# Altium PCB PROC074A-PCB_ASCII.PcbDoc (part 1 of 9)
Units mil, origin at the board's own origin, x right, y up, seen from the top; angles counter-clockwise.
Board outline 2755.91 x 5300 mil, 10 copper layers (Top Layer, L2-GND, L3-SIG1, L4-GND, L5-PWR/SIG, L6-SIG2, L7-PWR2, L8-SIG3, L9-GND, Bottom Layer), stack 67.57 mil thick; 586 components, 490 nets, 2137 pads, 1150 vias.
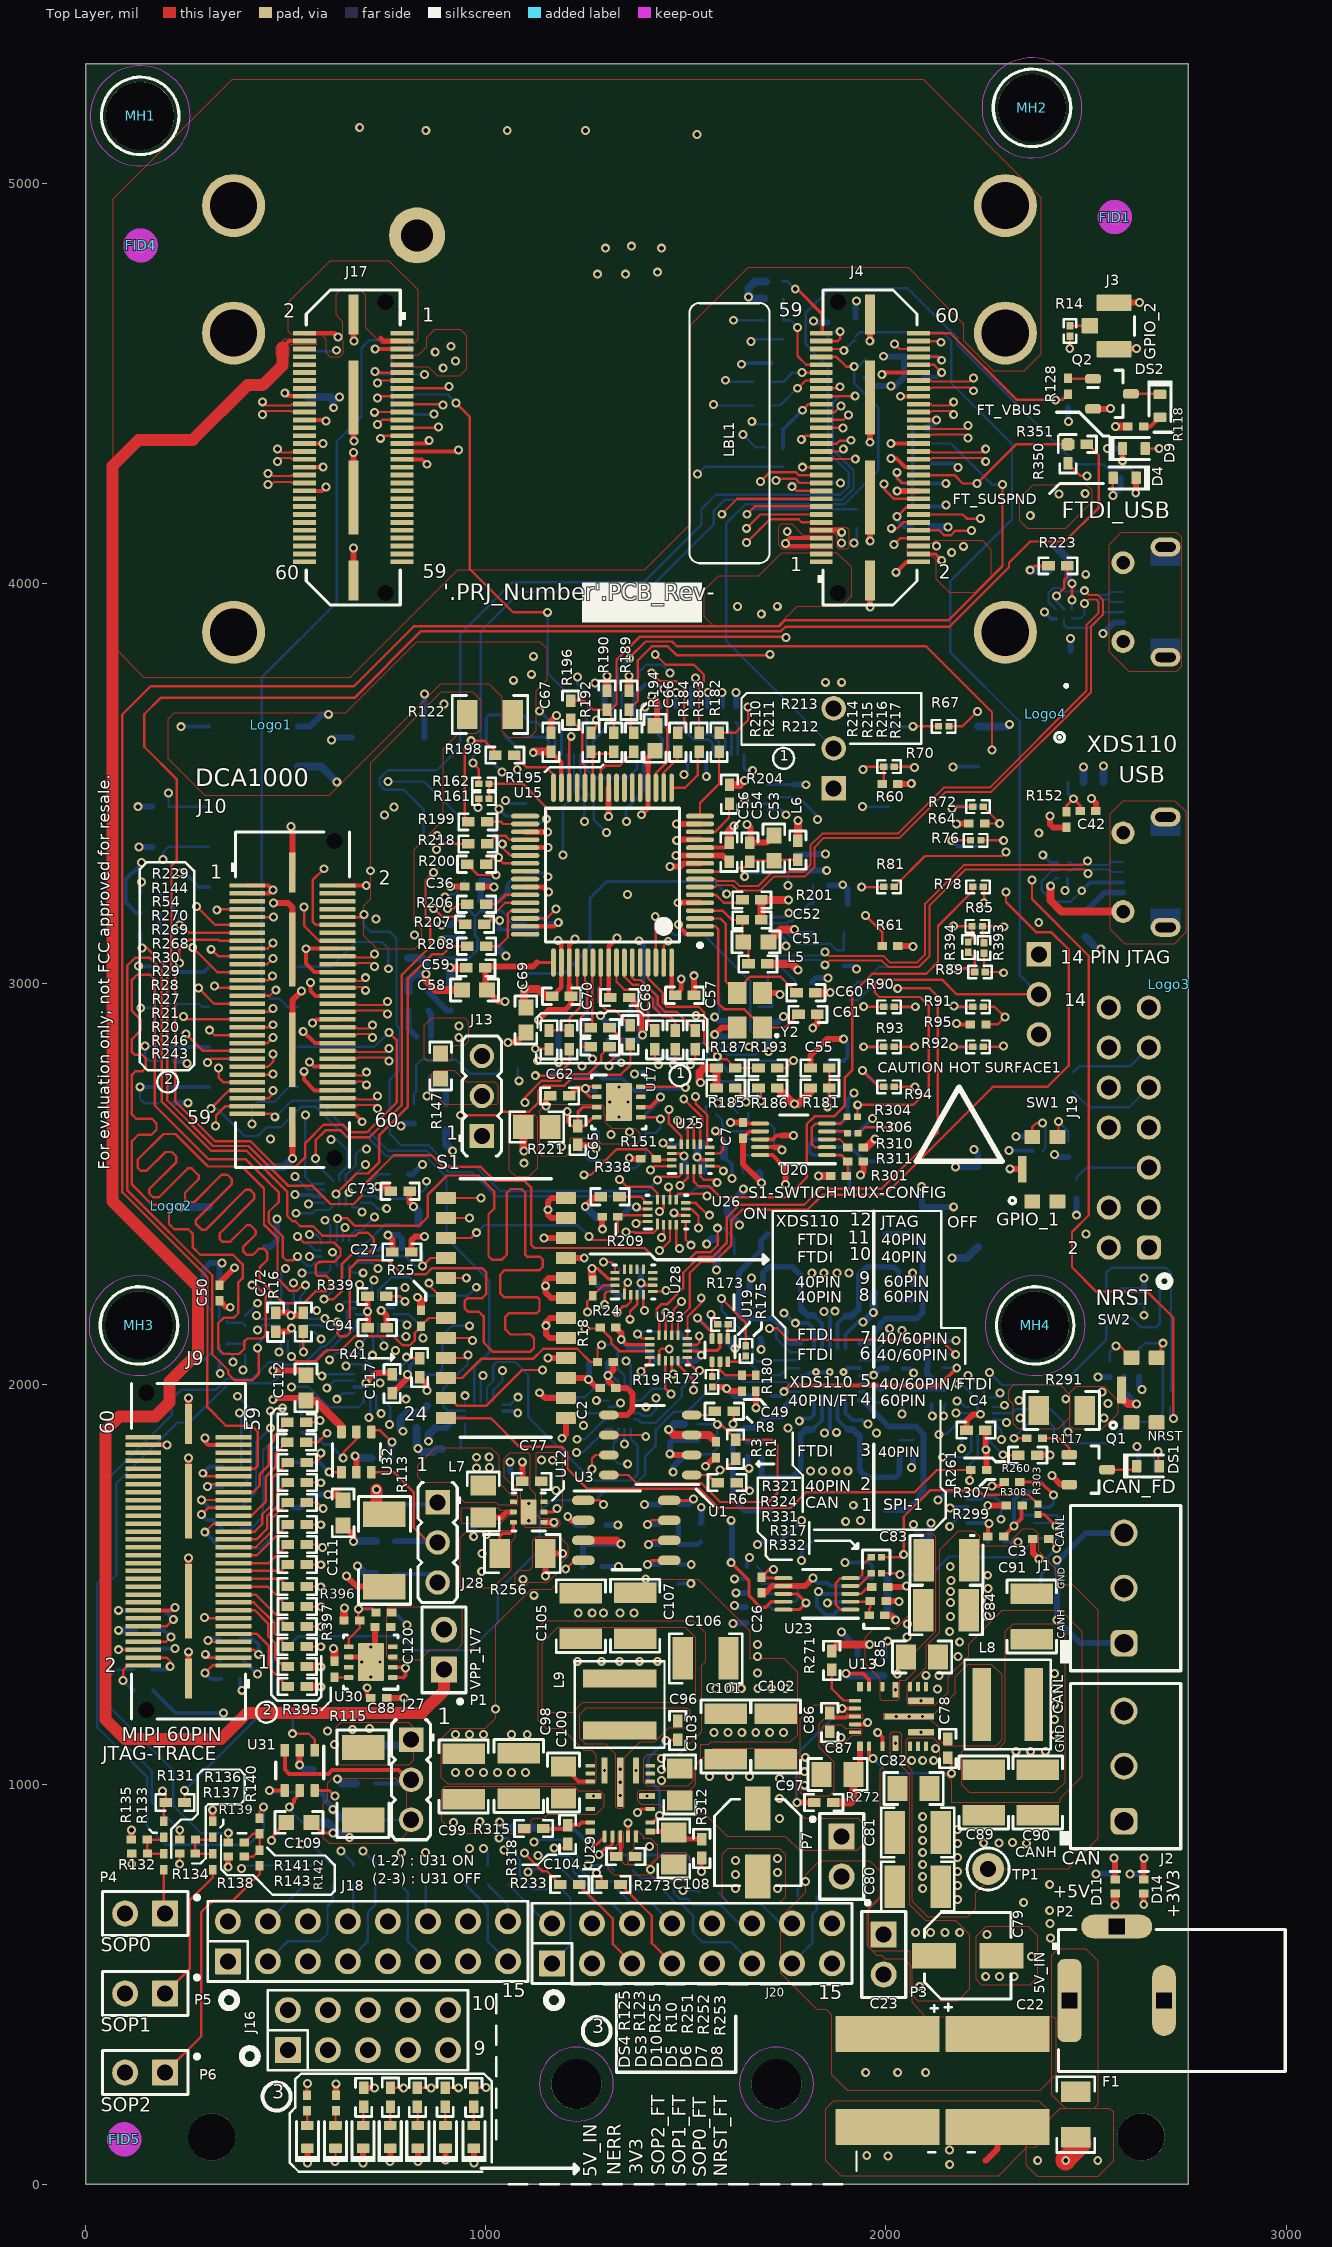
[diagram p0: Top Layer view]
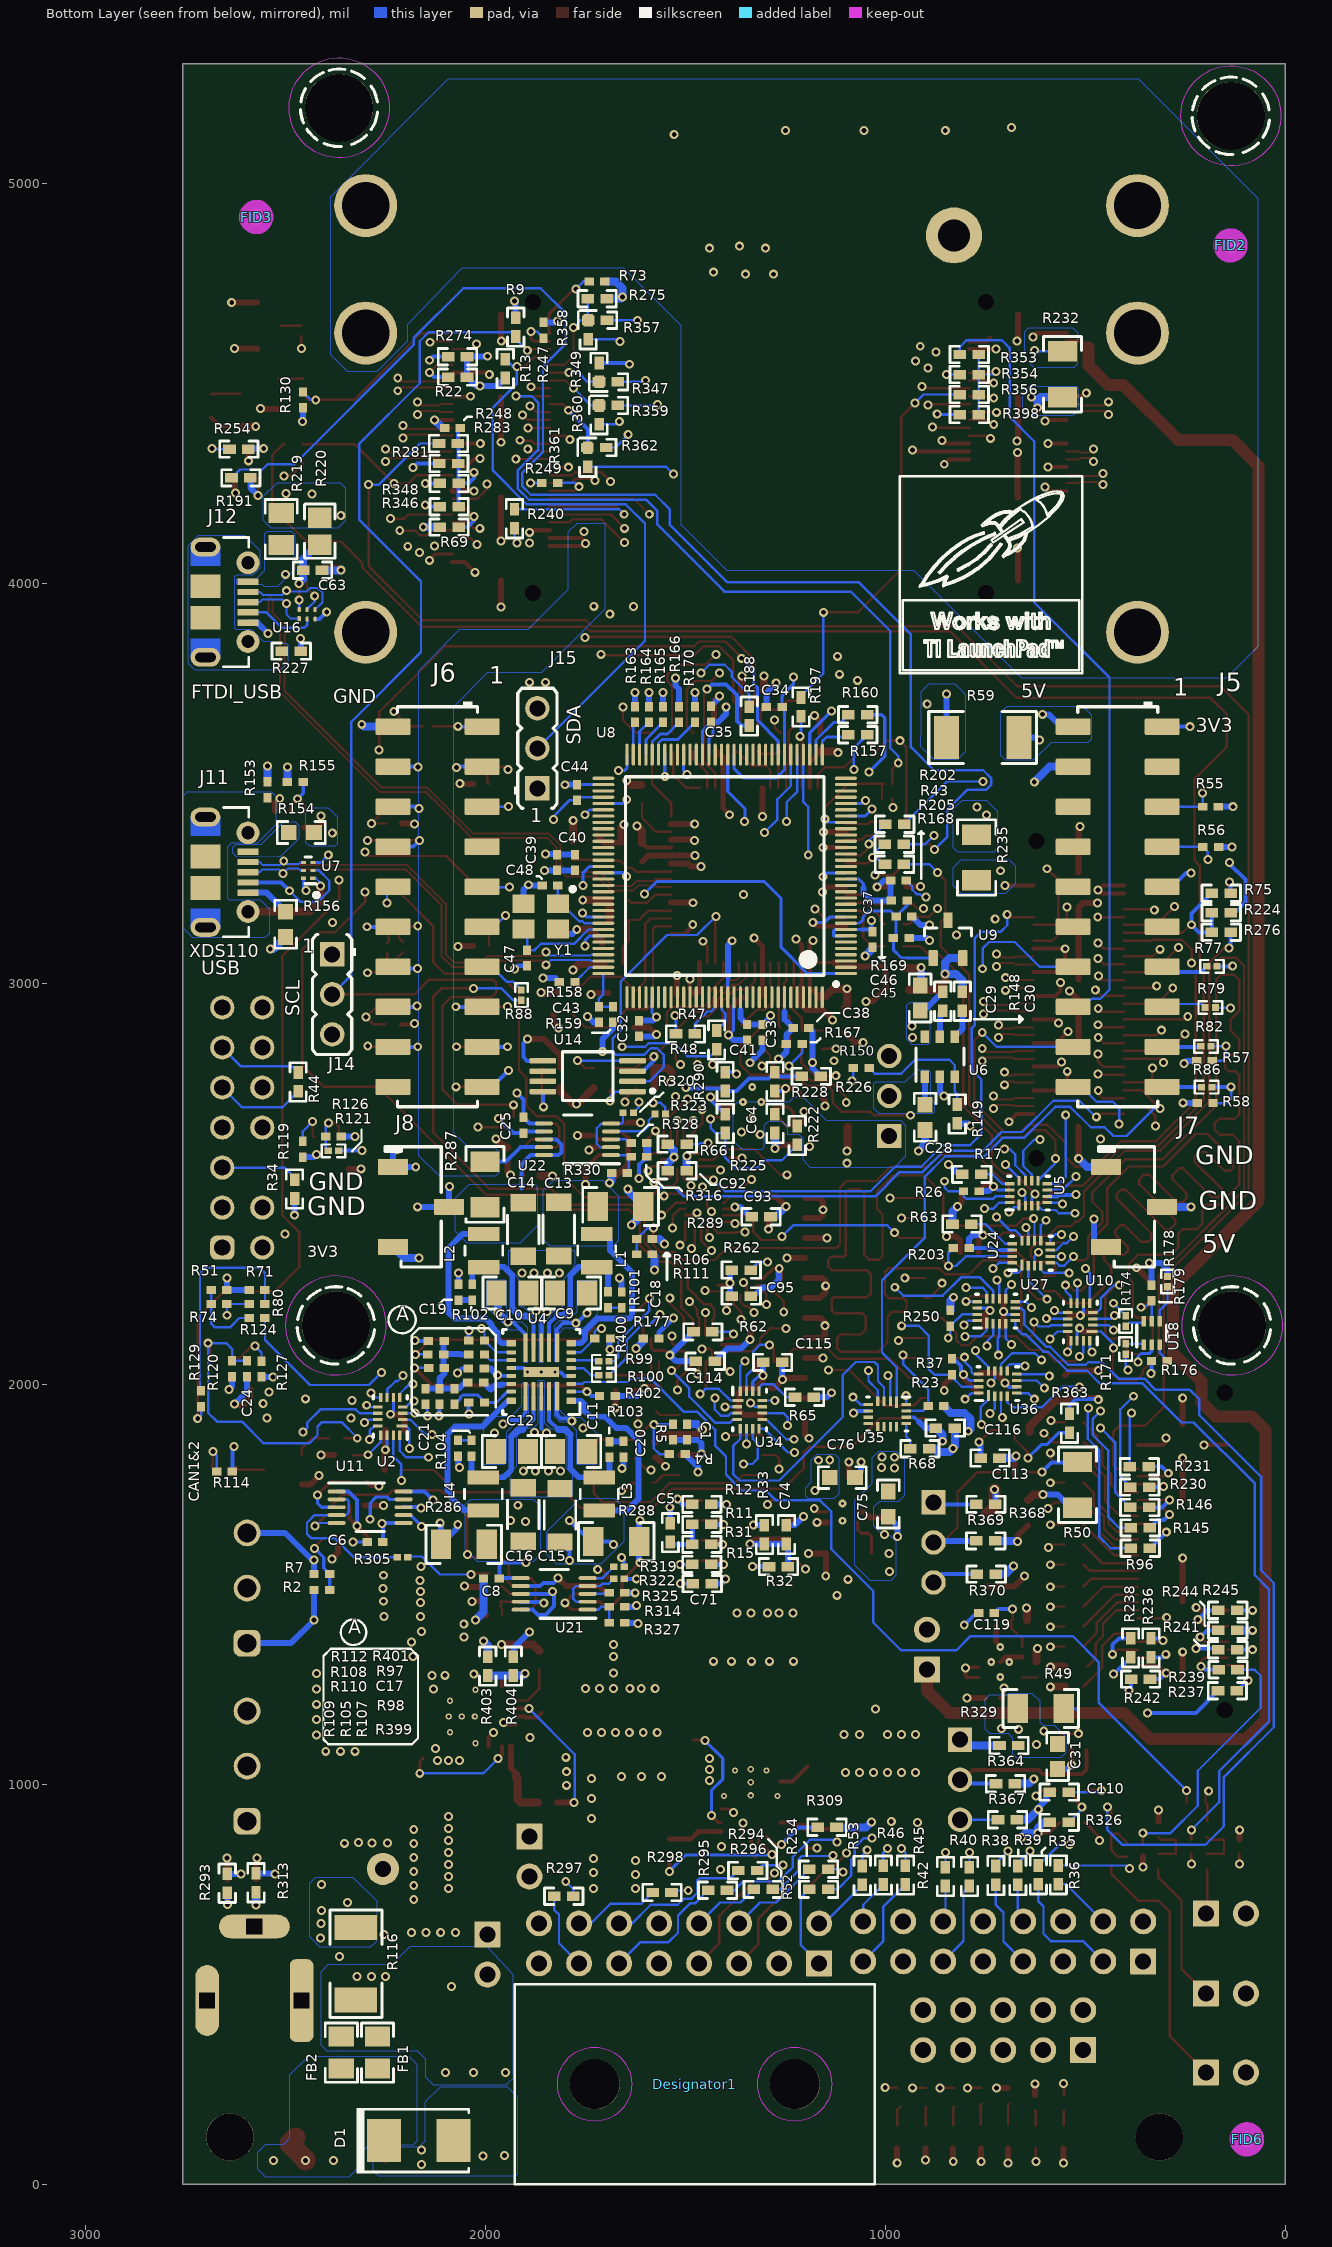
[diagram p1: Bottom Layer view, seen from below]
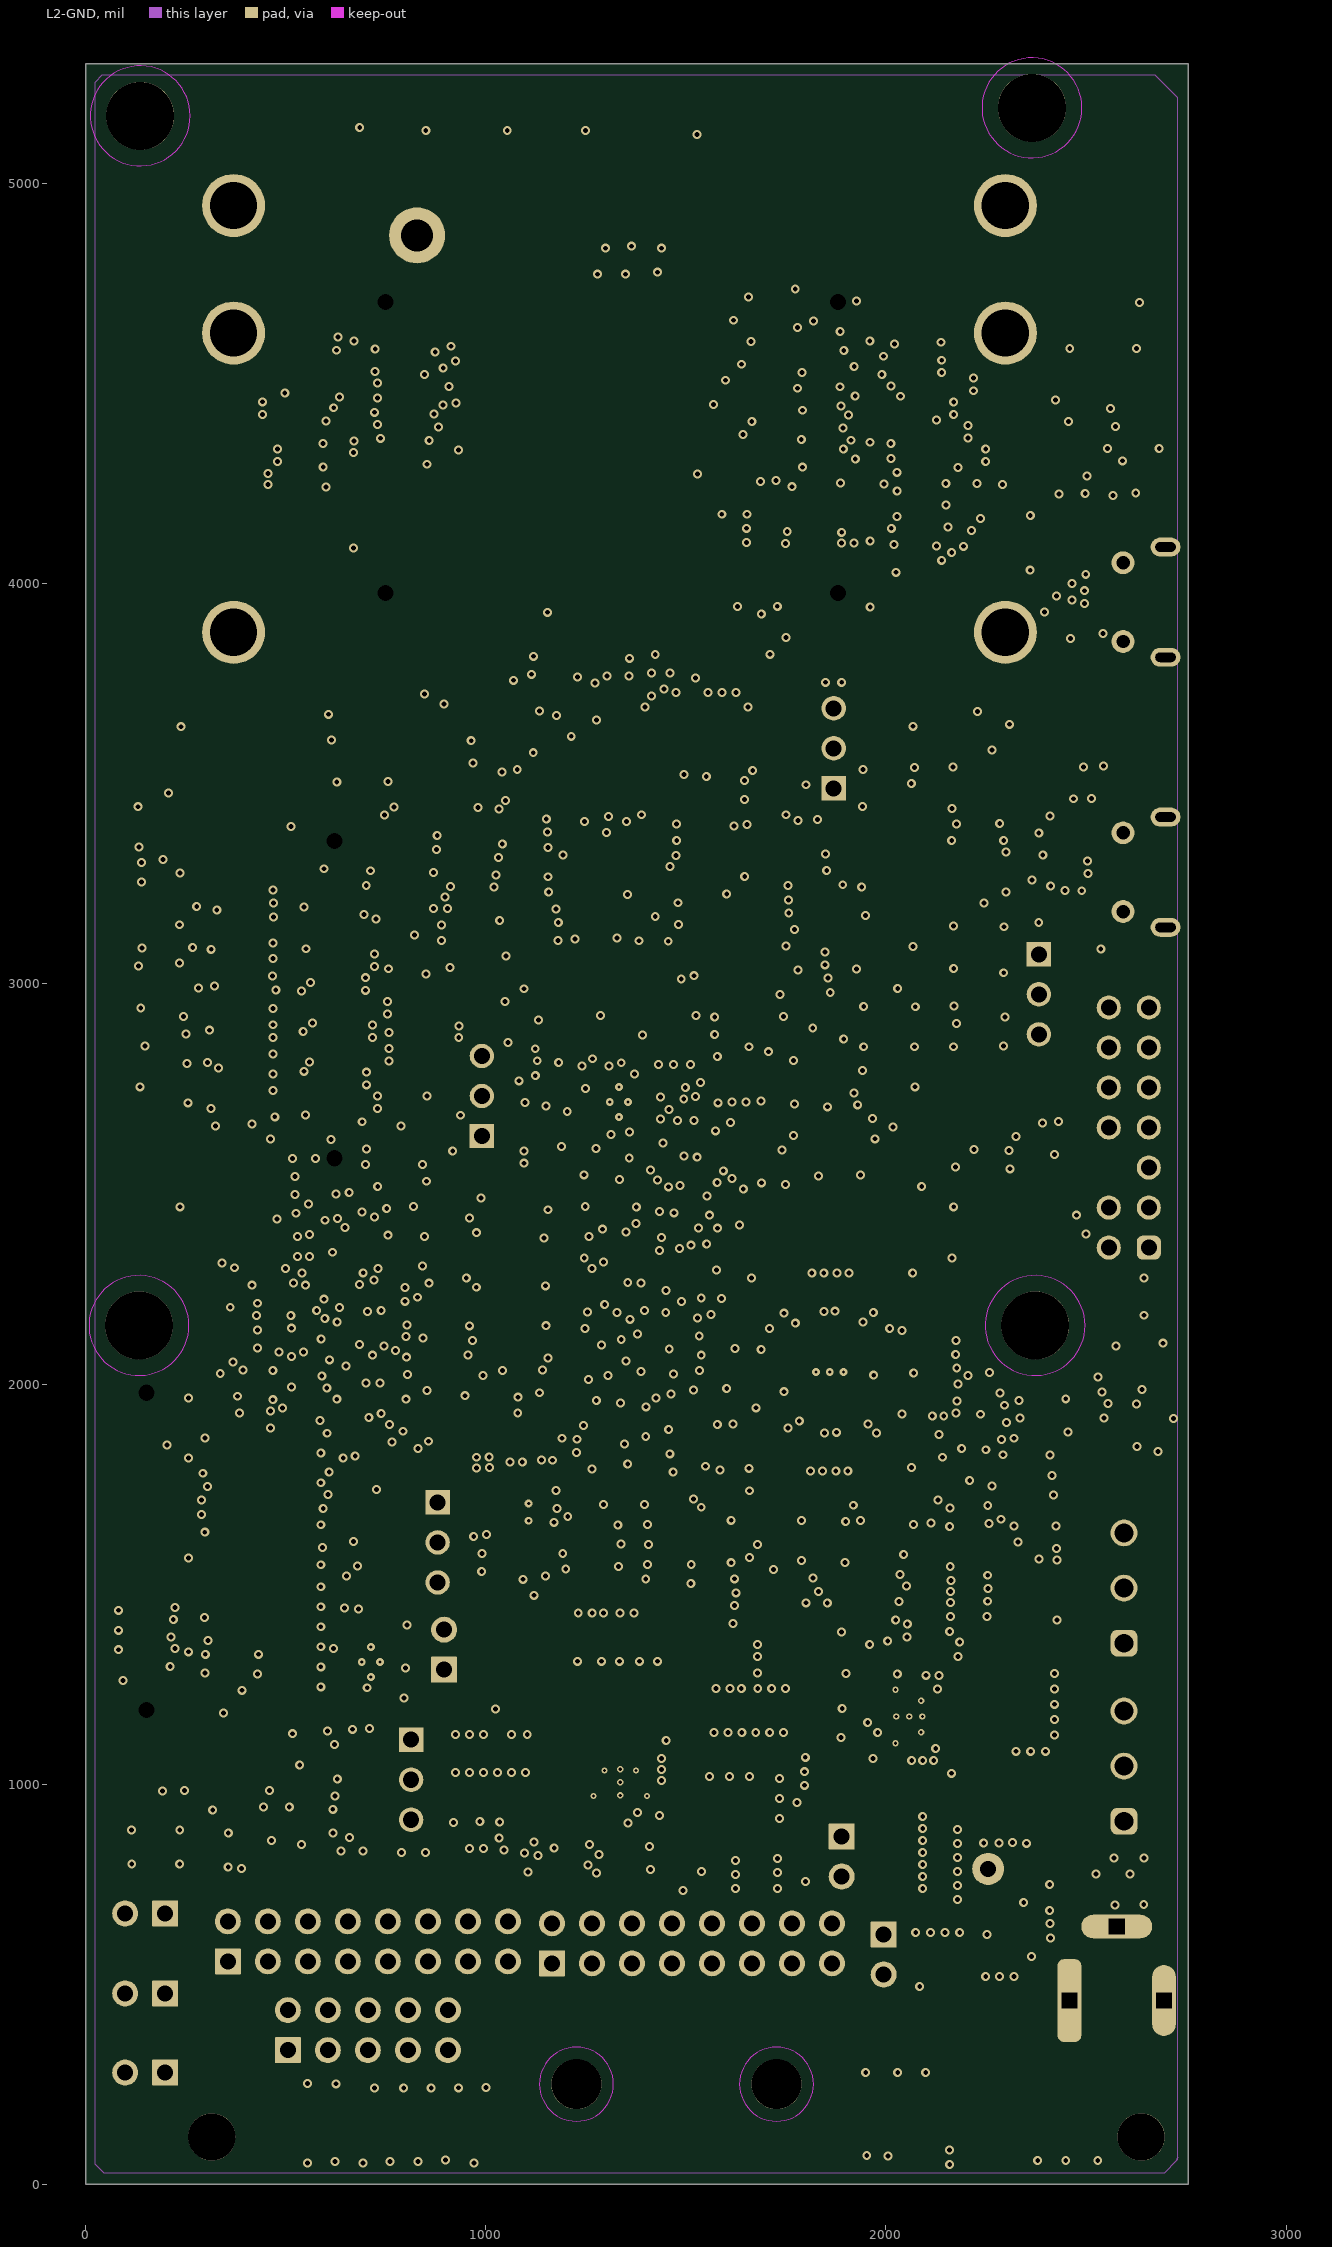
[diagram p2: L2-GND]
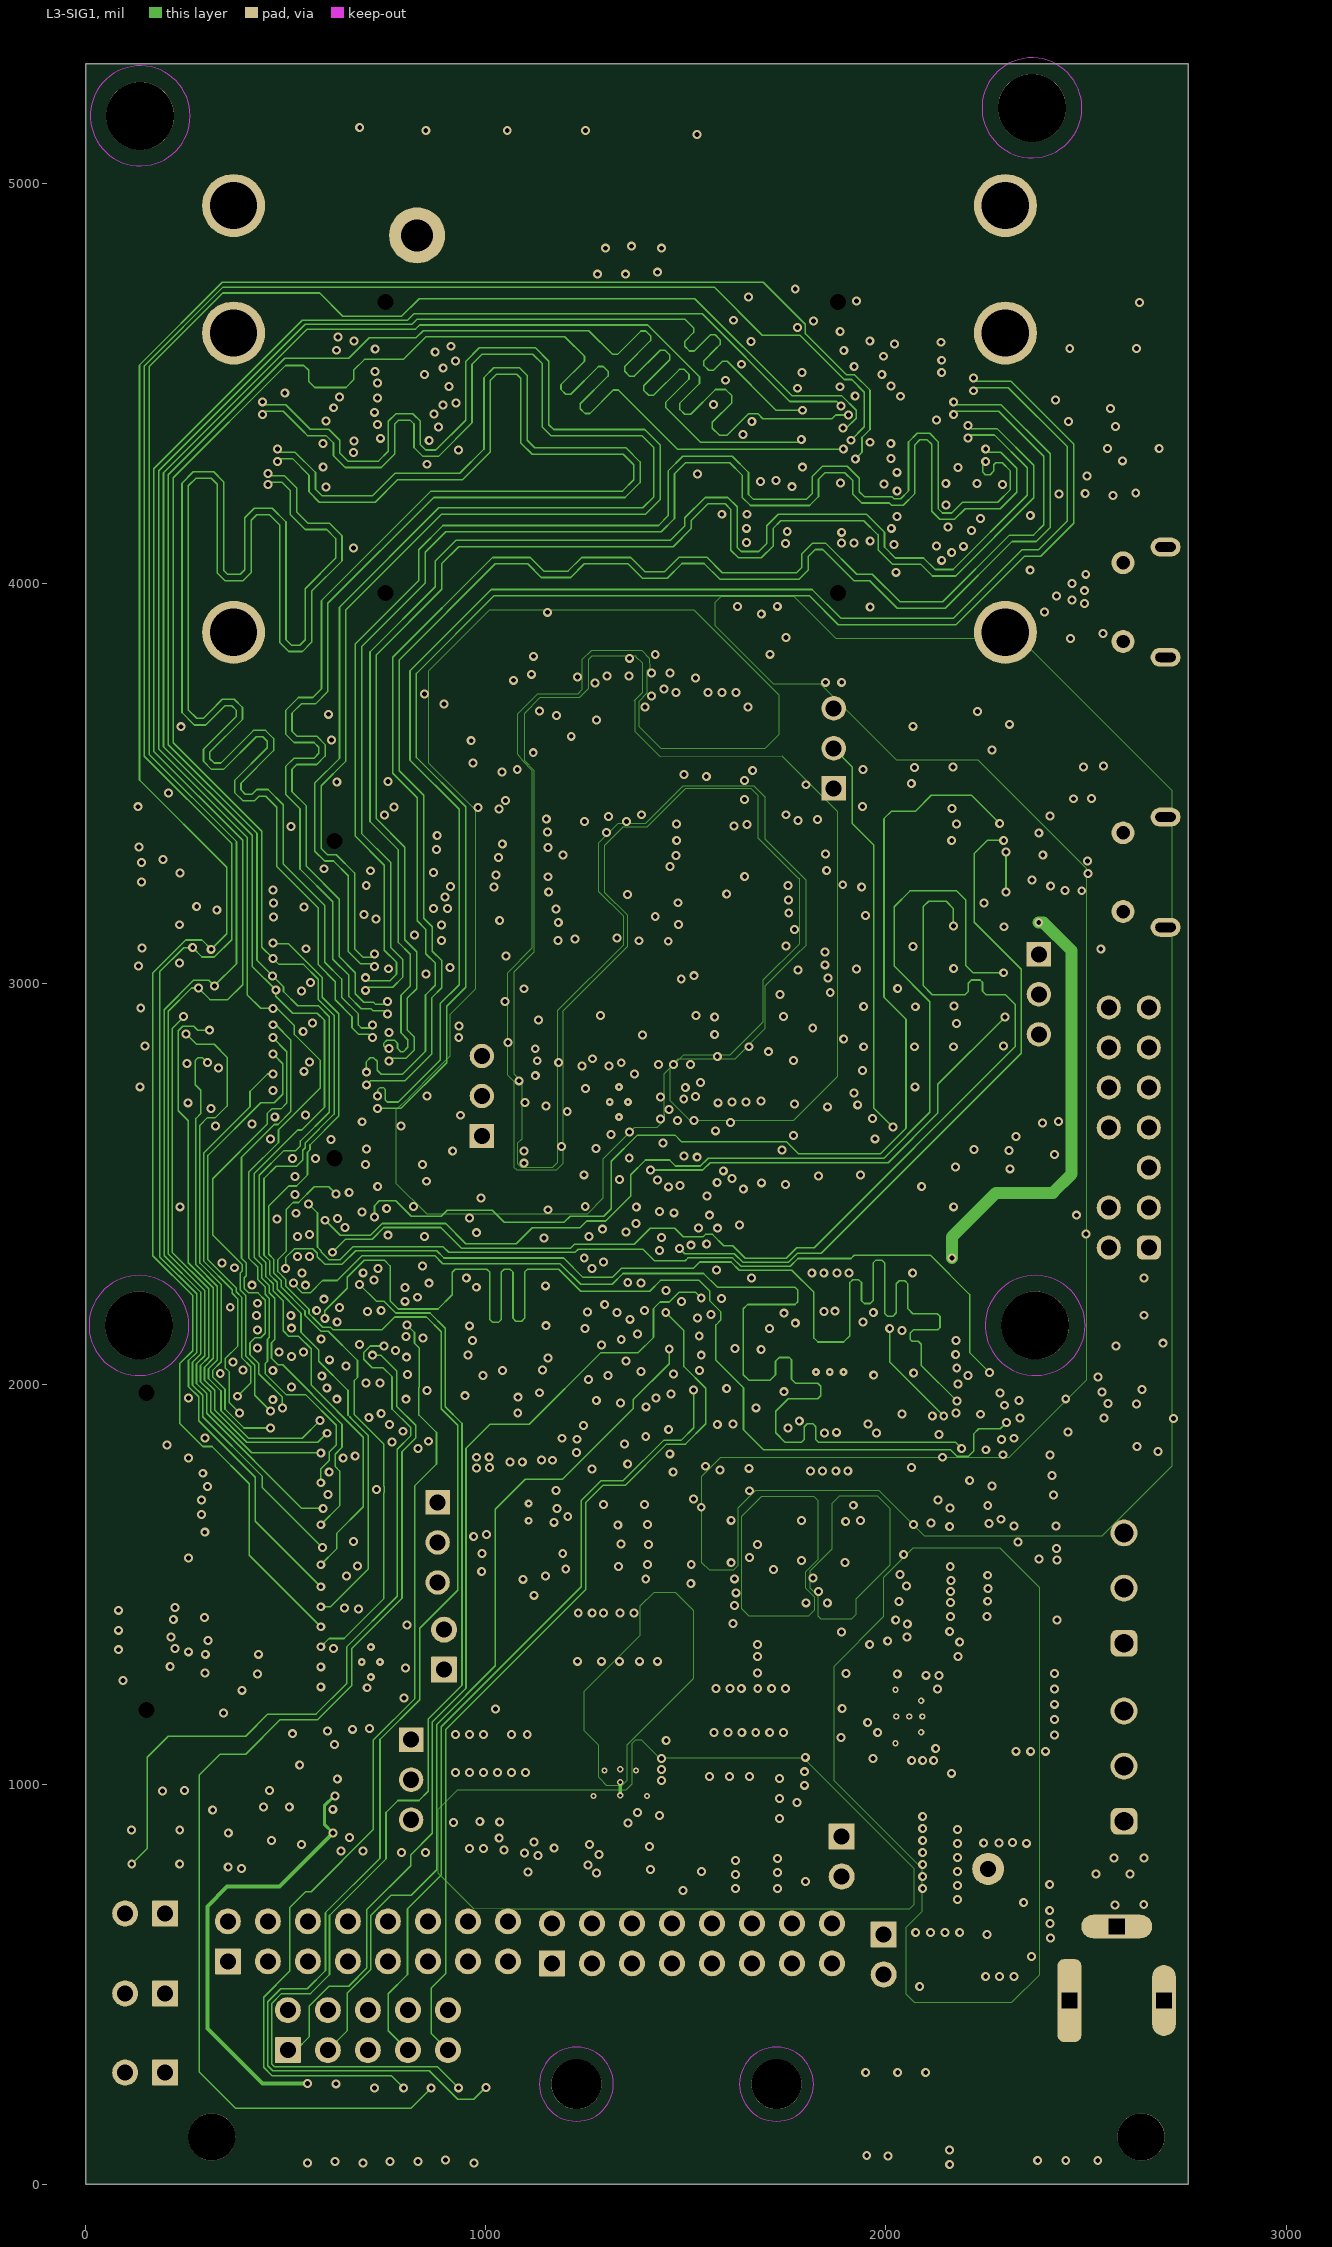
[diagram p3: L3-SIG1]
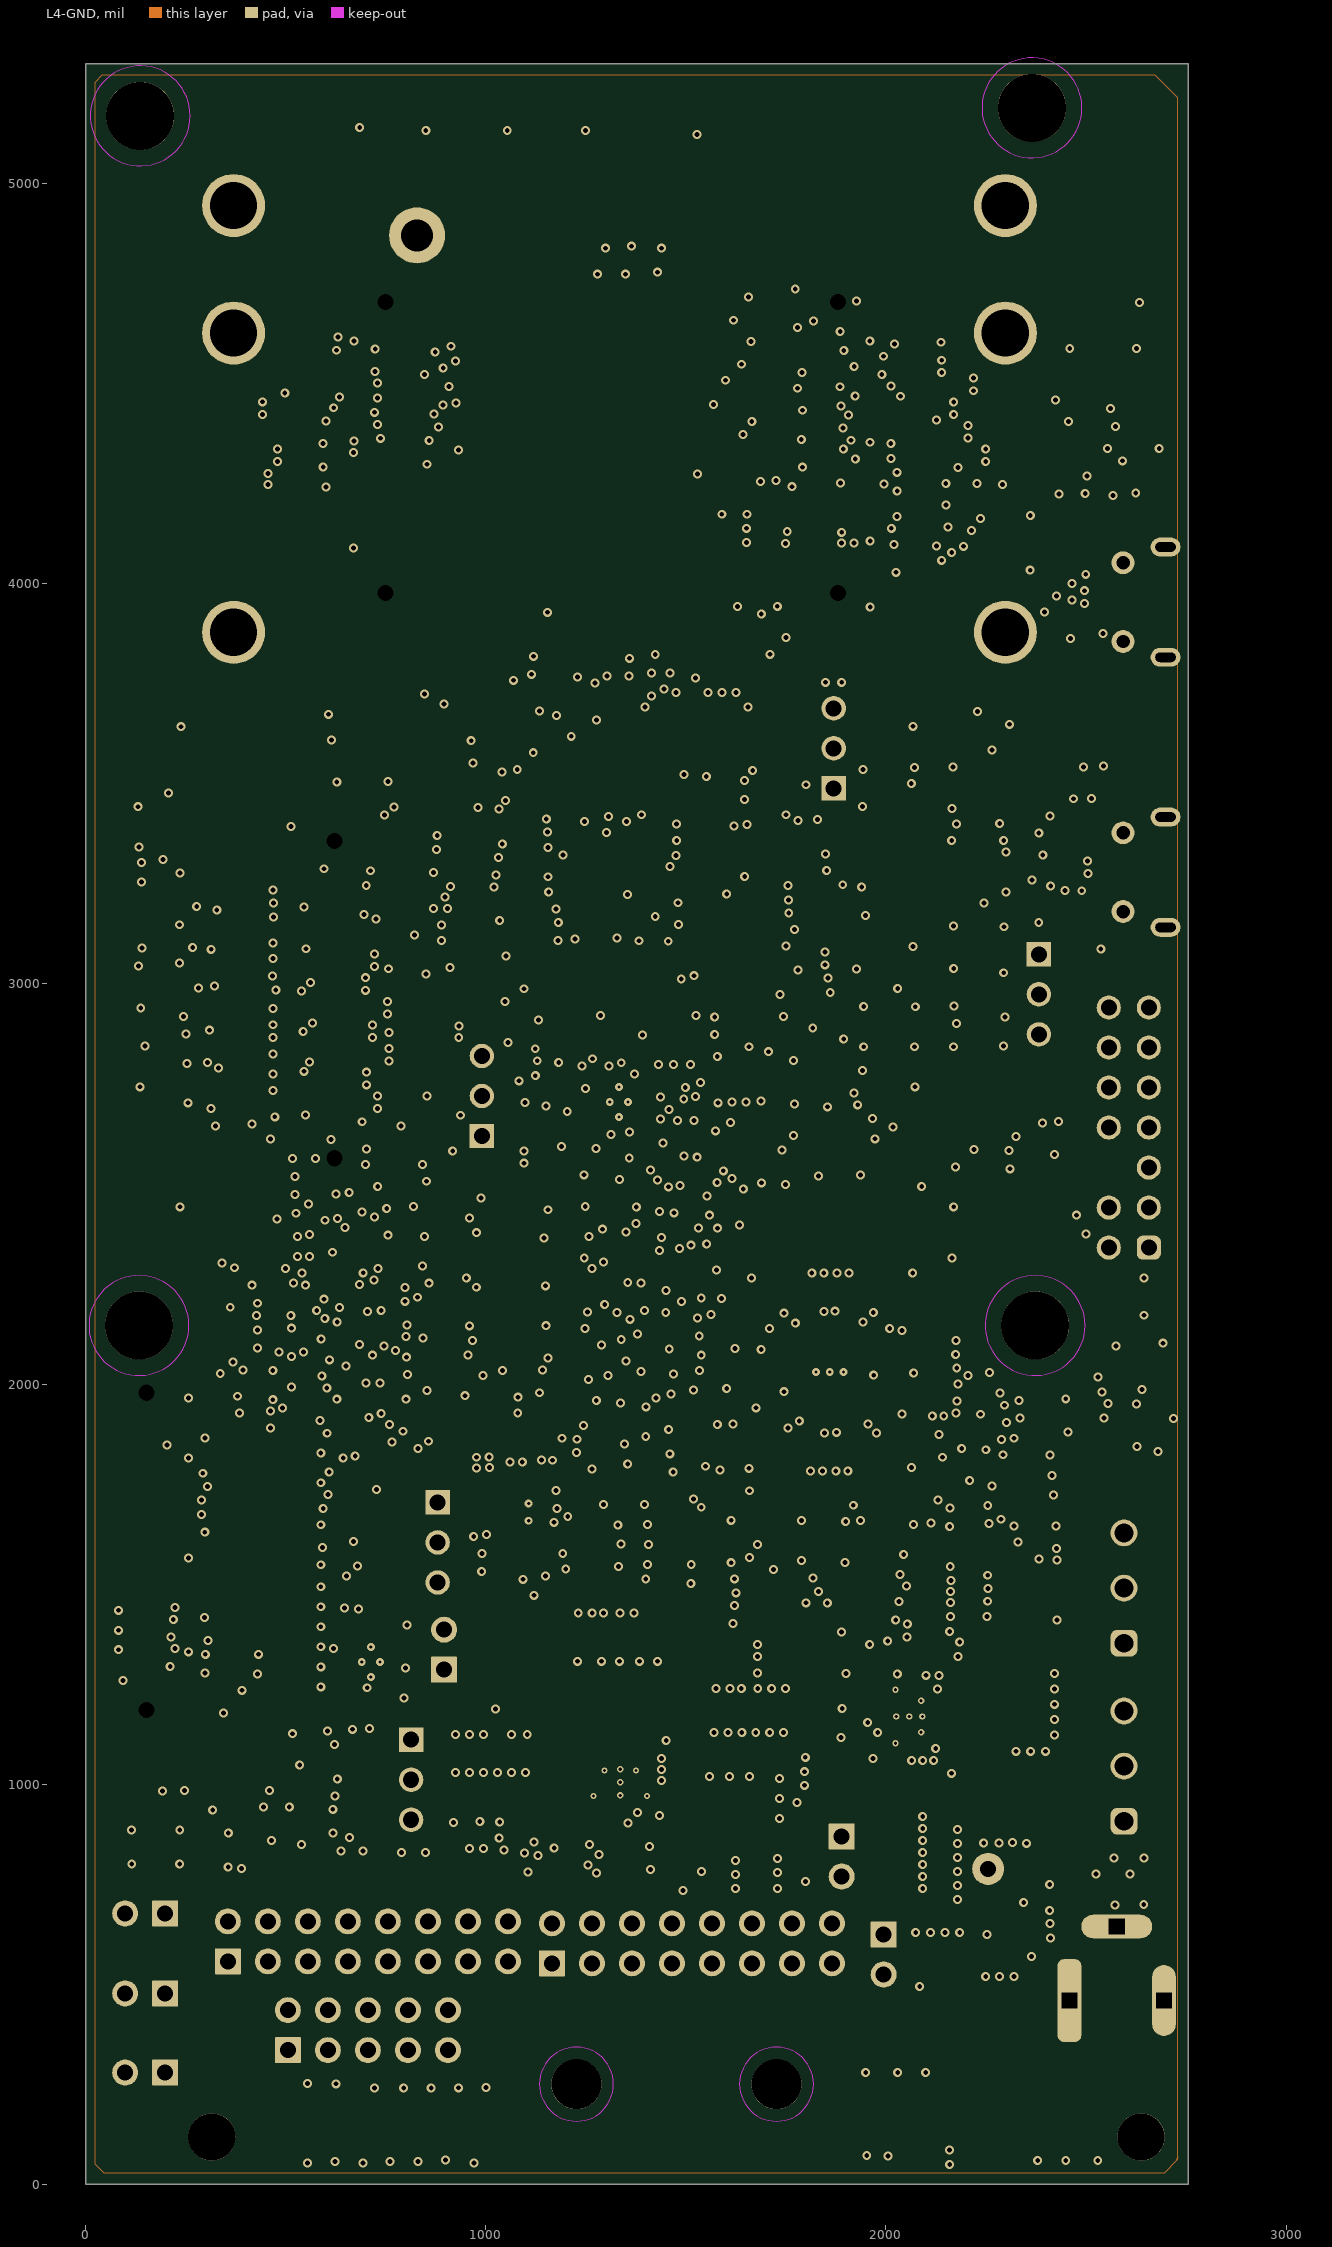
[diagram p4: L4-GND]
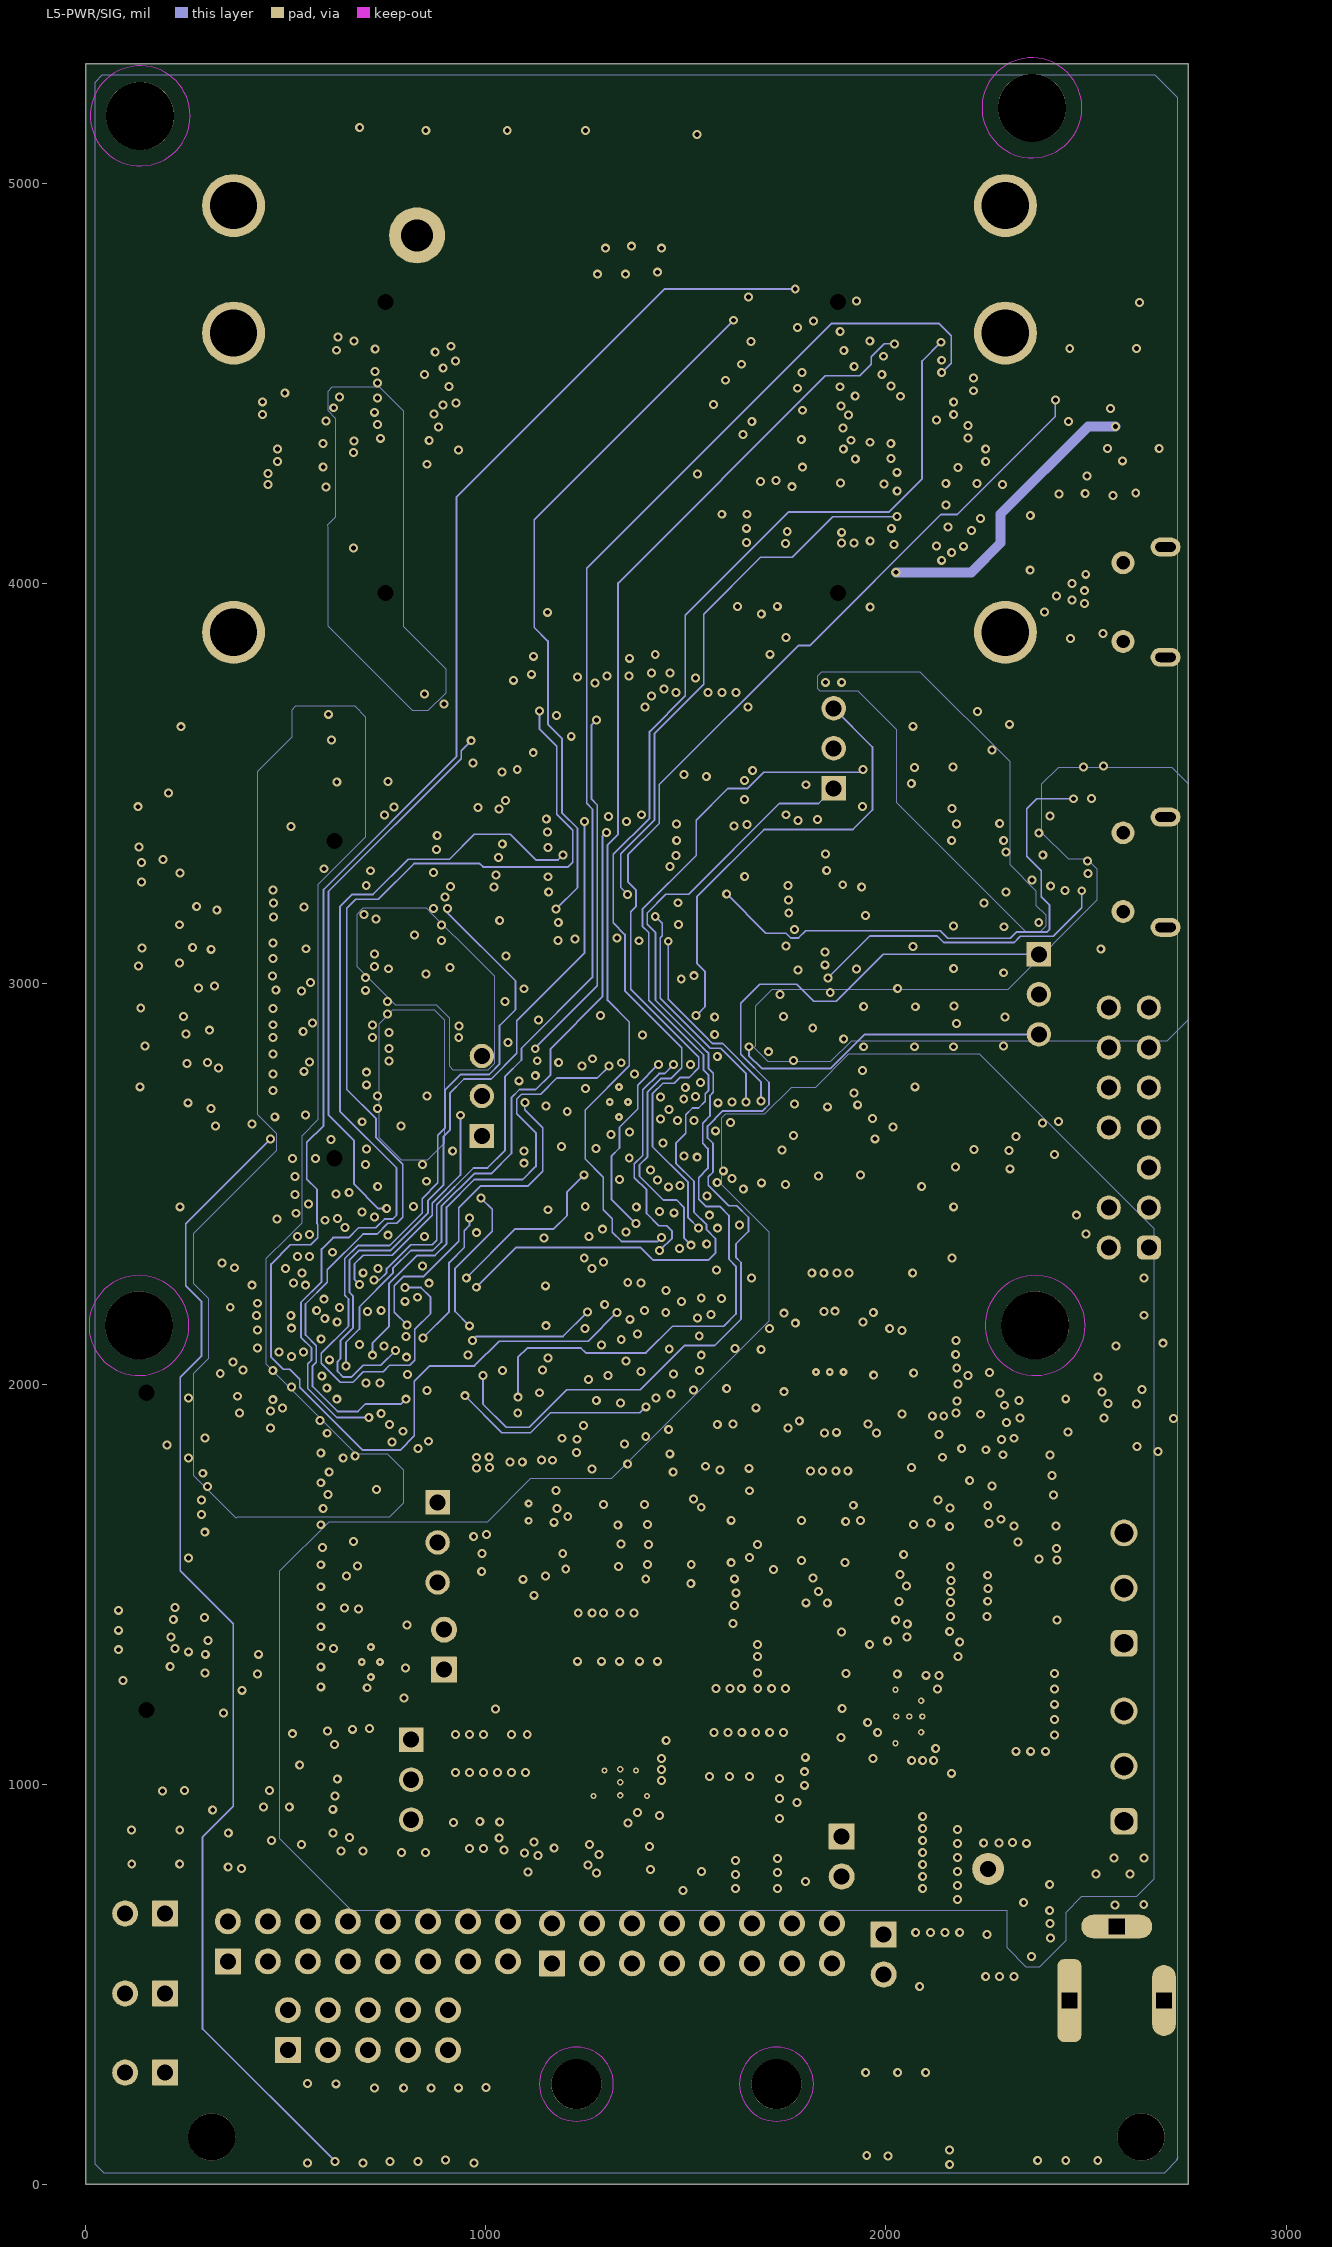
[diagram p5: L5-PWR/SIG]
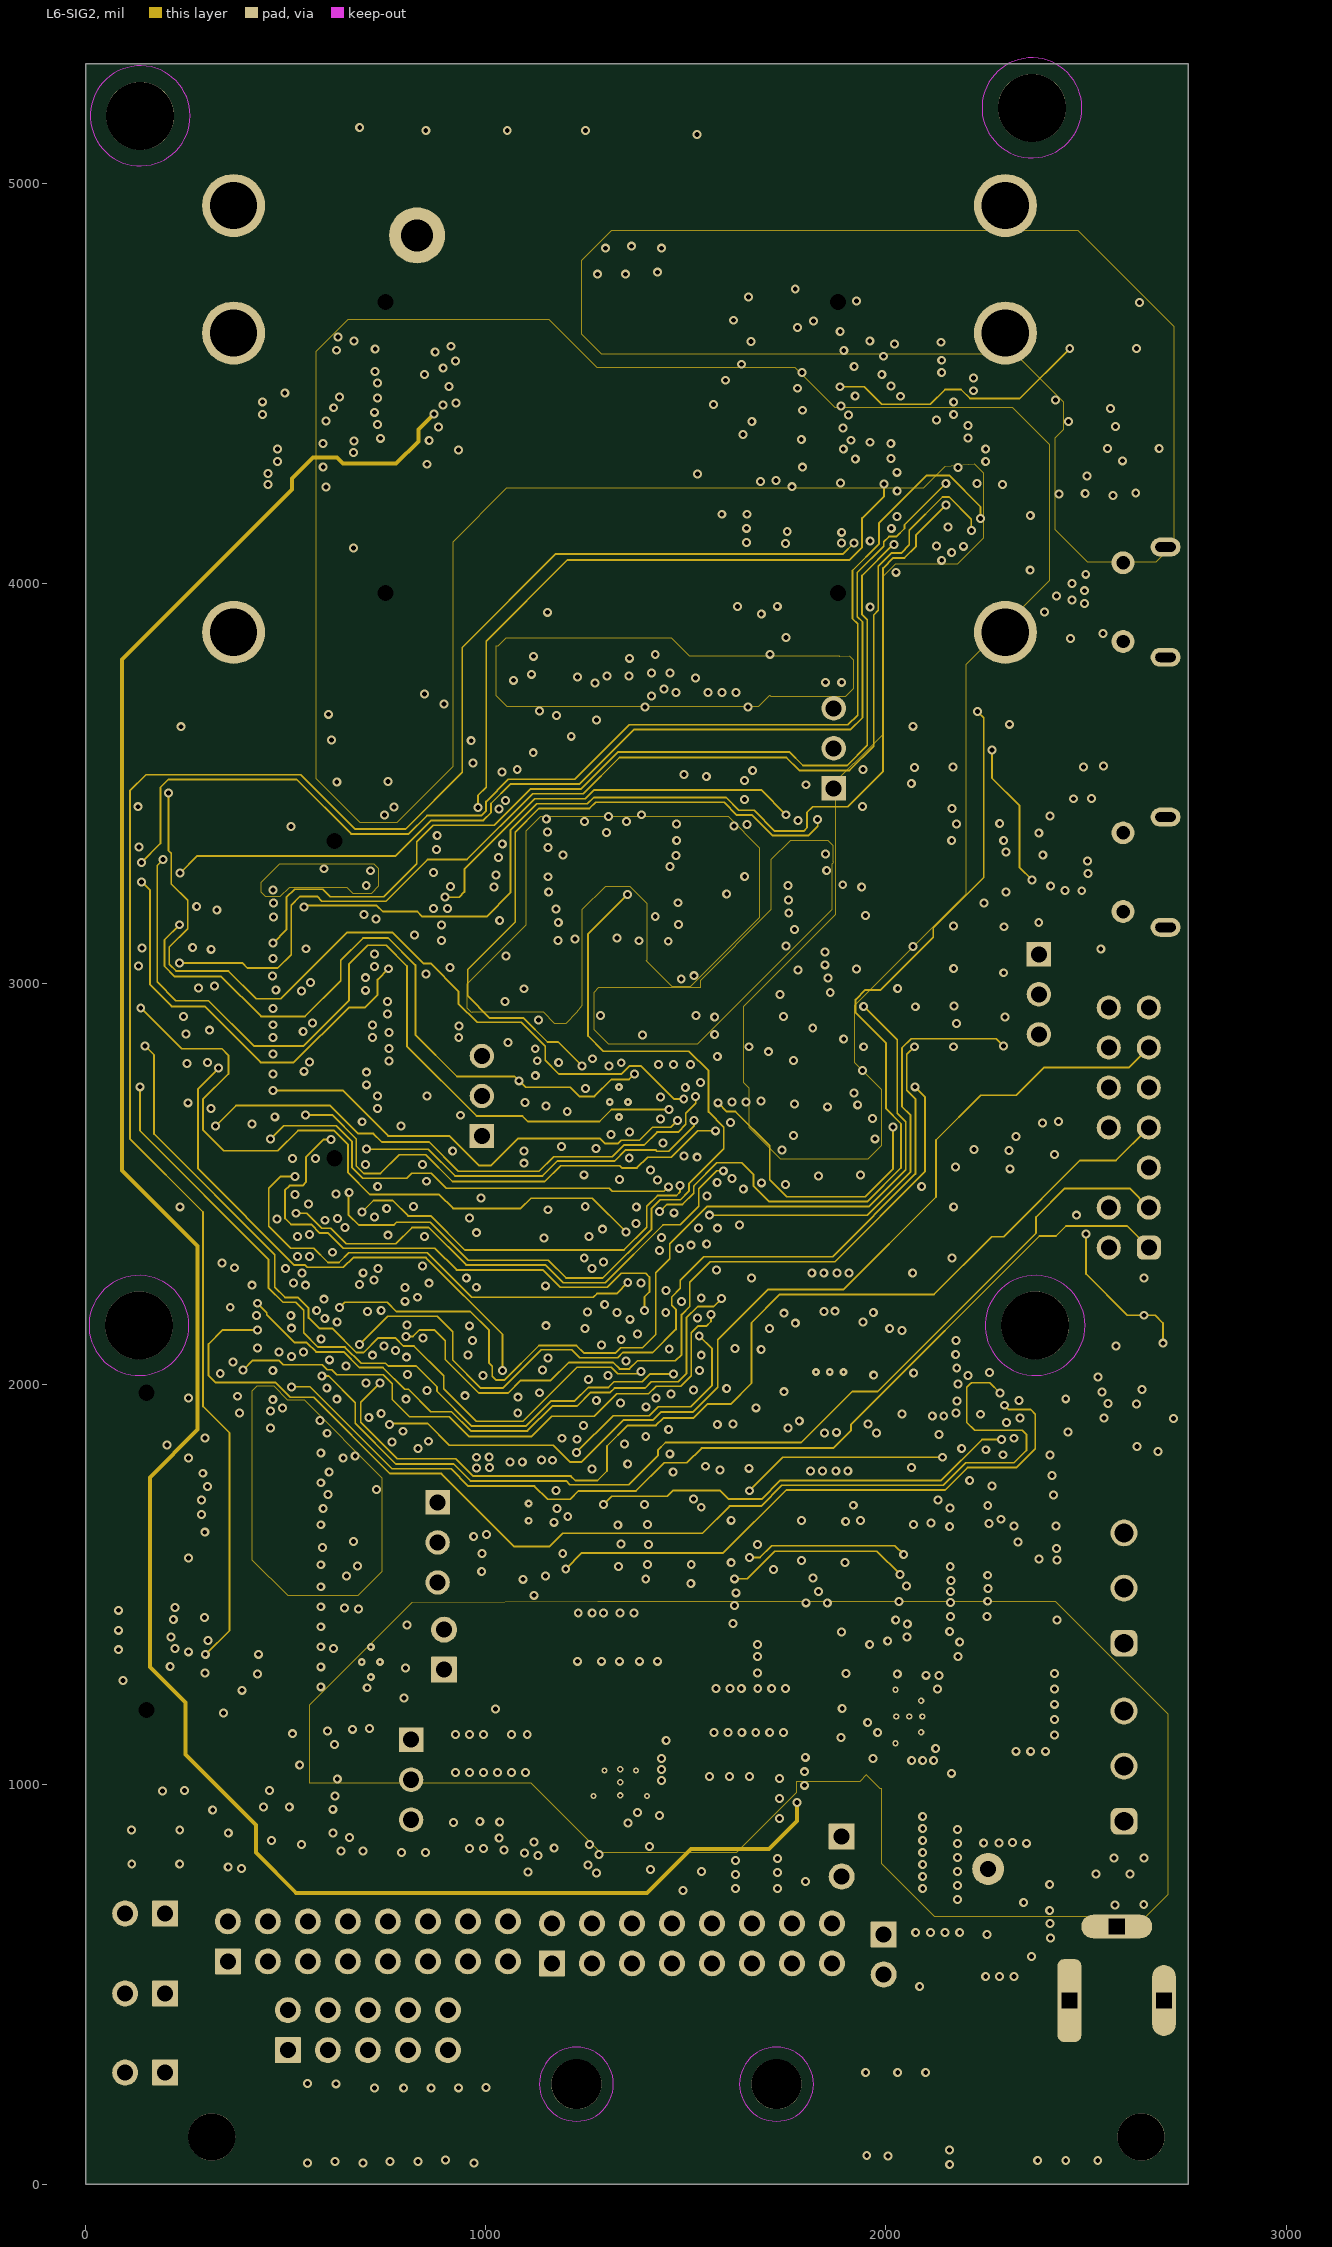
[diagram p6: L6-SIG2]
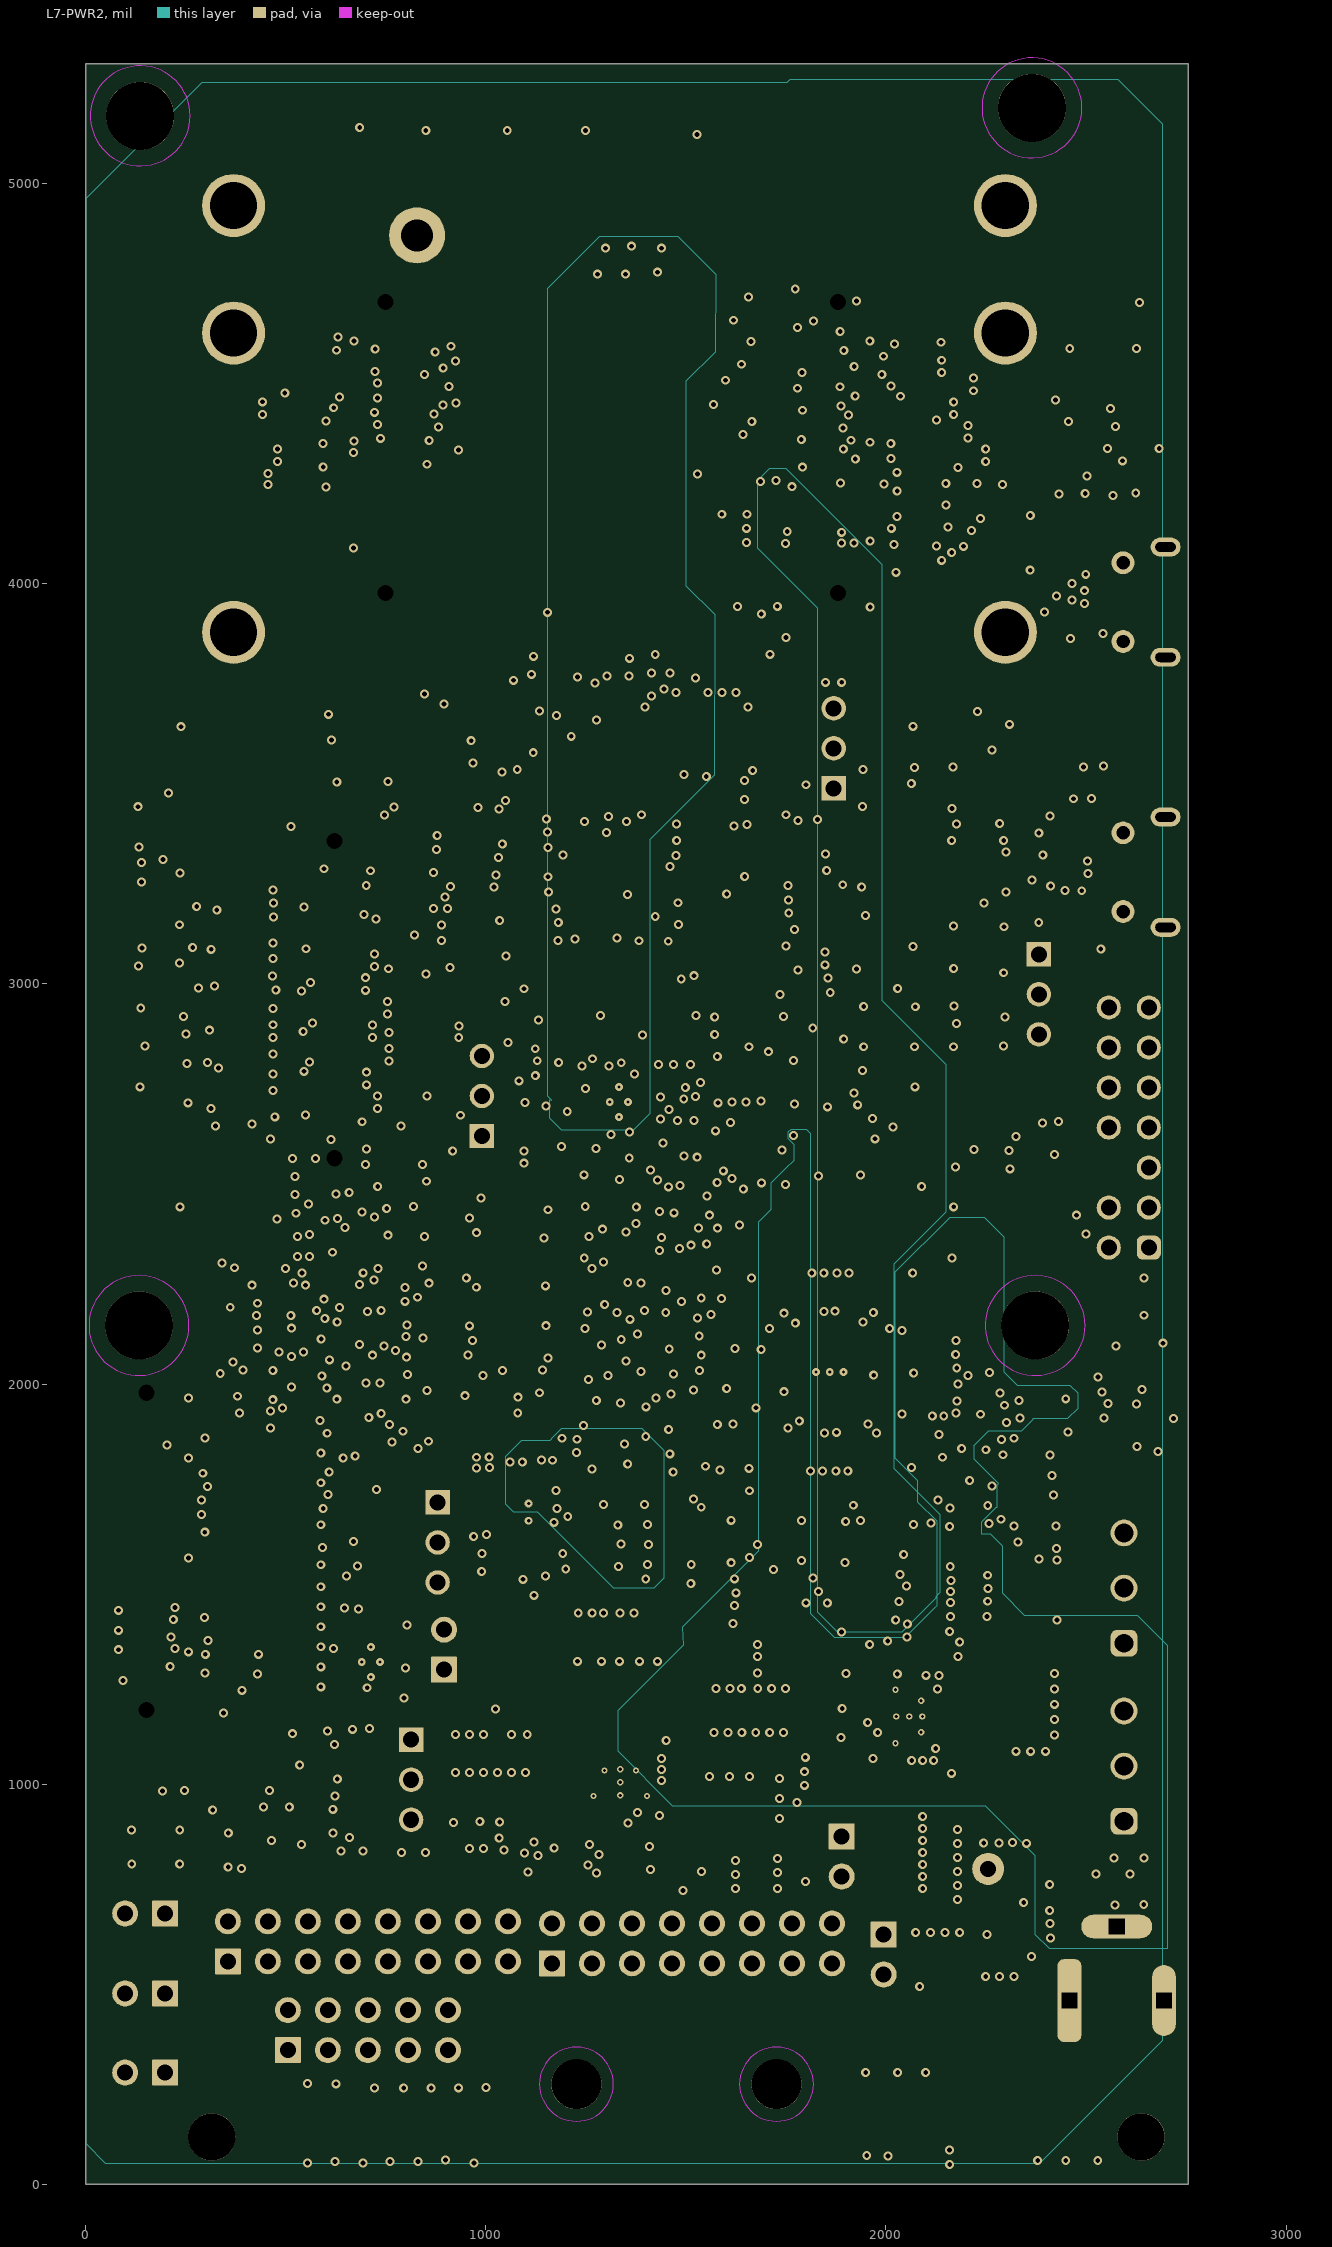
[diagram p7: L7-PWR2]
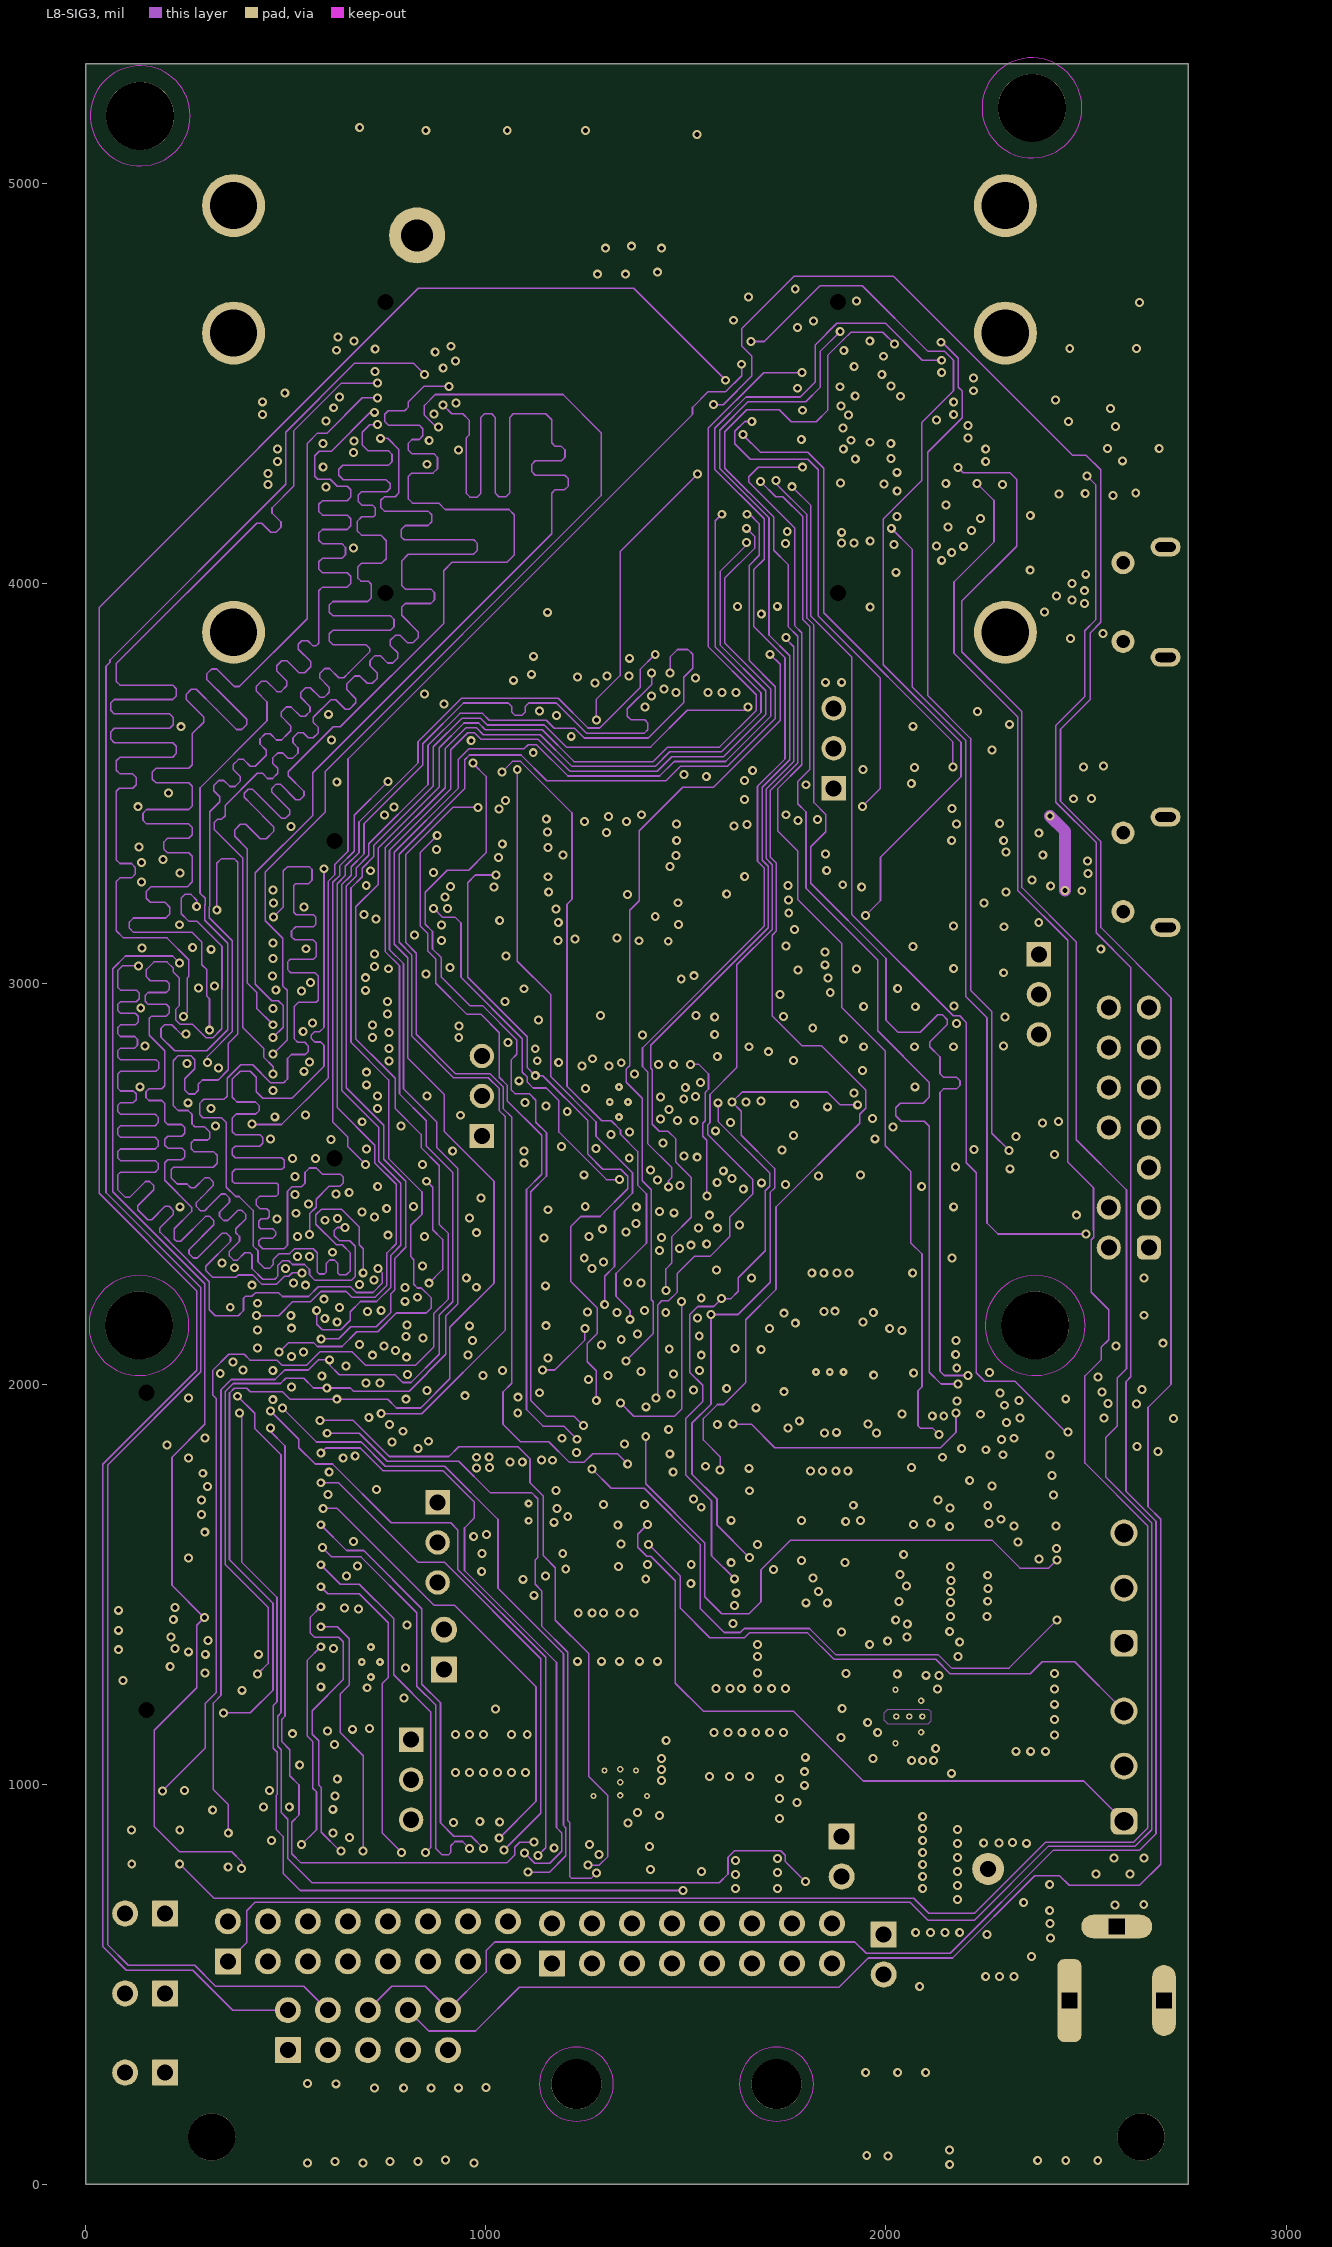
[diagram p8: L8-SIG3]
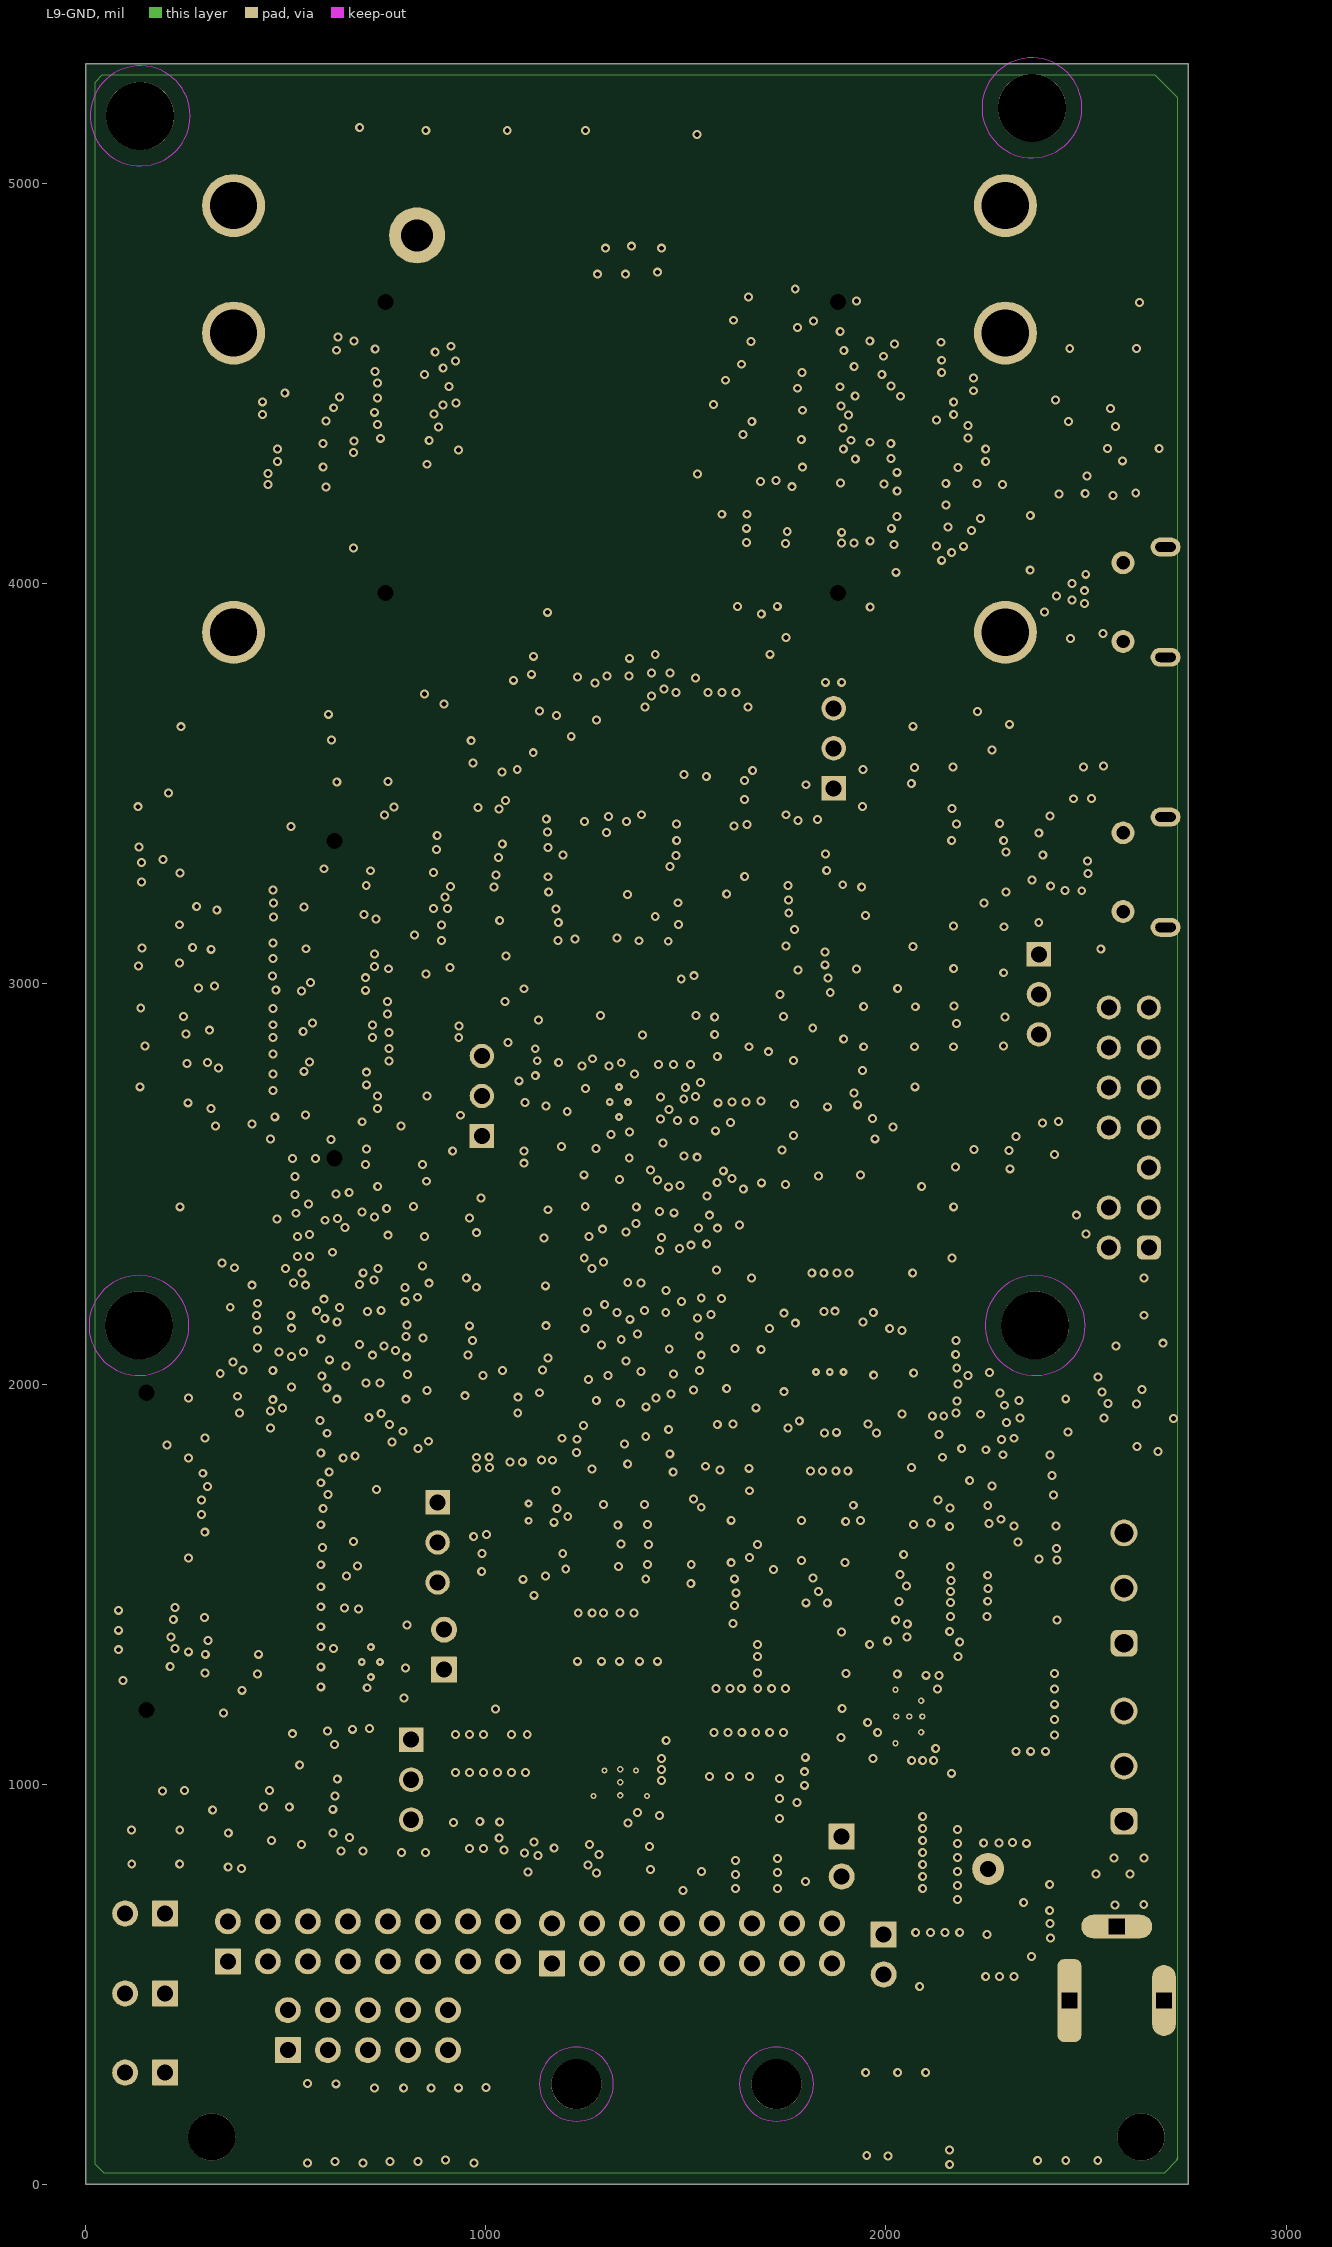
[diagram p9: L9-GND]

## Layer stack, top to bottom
Top Solder: solder mask 0.8, Solder Resist, Dk 1
Top Layer: signal copper 1.8
Dielectric1: prepreg 3.87, FR-4, Dk 4.02
L2-GND: signal copper 1.2
Dielectric 2: core 4, FR-4, Dk 4.26
L3-SIG1: signal copper 1.2
Dielectric 3: prepreg 8.7, FR-4, Dk 4.06
L4-GND: signal copper 1.2
Dielectric 4: core 4, FR-4, Dk 4.26
L5-PWR/SIG: signal copper 1.2
Dielectric 5: prepreg 13.51, FR-4, Dk 4.06
L6-SIG2: signal copper 1.2
Dielectric 6: core 4, FR-4, Dk 4.26
L7-PWR2: signal copper 1.2
Dielectric 7: prepreg 8.42, FR-4, Dk 4.06
L8-SIG3: signal copper 1.2
Dielectric 8: core 4, FR-4, Dk 4.26
L9-GND: signal copper 1.2
Dielectric 9: prepreg 3.87, FR-4, Dk 4.02
Bottom Layer: signal copper 1.8
Bottom Solder: solder mask 0.8, Solder Resist, Dk 1

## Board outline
0,0 0,5300 2755.91,5300 2755.91,0

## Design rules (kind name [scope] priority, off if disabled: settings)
AcuteAngle [All] p0: scope1count=1 scope1_0_kind=Board scope1_0_value=Board scope2count=1 scope2_0_kind=Board scope2_0_value=Board commentlength=0 minimum=4.50000000000000E+0001
AcuteAngle [All] p1: minimum=4.50000000000000E+0001 checktracksonly=TRUE
AssemblyTestPointUsage [All] p0: scope1count=1 scope1_0_kind=Board scope1_0_value=Board scope2count=1 scope2_0_kind=Board scope2_0_value=Board commentlength=0
AssemblyTestPointUsage [All] p1: valid=2
AssemblyTestpoint [All] p0: scope1count=1 scope1_0_kind=Board scope1_0_value=Board scope2count=1 scope2_0_kind=Board scope2_0_value=Board commentlength=0
BoardOutlineClearance [All] p0 off: scope1count=1 scope1_0_kind=Board scope1_0_value=Board scope2count=1 scope2_0_kind=Board scope2_0_value=Board commentlength=172 gap=19 // Protel DXP Scope 1 Expression Was: OnCopper and Not InComponentClass('Logo') and not InComponentClass('FiducialMark') and not InRegion(1000,500,4000,800) and not InPoly
BoardOutlineClearance BoardOutlineClearance_Poly [All] p0 off: scope1count=1 scope1_0_kind=Board scope1_0_value=Board scope2count=1 scope2_0_kind=Board scope2_0_value=Board commentlength=58 gap=25 // Protel DXP Scope 1 Expression Was: OnCopper and IsPoly
BoardOutlineClearance BoardOutlineClearance_MountingHoles [All] p0 off: scope1count=1 scope1_0_kind=Board scope1_0_value=Board scope2count=1 scope2_0_kind=Board scope2_0_value=Board commentlength=86 gap=40 // Protel DXP Scope 1 Expression Was: OnCopper and InComponentClass('Mounting Holes')
BoardOutlineClearance BoardOutlineClearance_MountingHoles [OnCopper and InComponentClass('Mounting Holes')] p1: gap=40 ignorepadtopadclearanceinfootprint=FALSE
BoardOutlineClearance BoardOutlineClearance_Poly [OnCopper and IsPoly] p2: gap=25 ignorepadtopadclearanceinfootprint=FALSE
BoardOutlineClearance [OnCopper and Not InComponentClass('Logo') and not InComponentClass('FiducialMark') and not InRegion(1000,500,4000,800) and not InPoly] p3: gap=19 ignorepadtopadclearanceinfootprint=FALSE
Clearance Clearance_2 [All] p0 off: scope1count=1 scope1_0_kind=Board scope1_0_value=Board scope2count=1 scope2_0_kind=Board scope2_0_value=Board commentlength=70 gap=5 // Protel DXP Scope 1 Expression Was: WithinRoom('Copper to PMIC IC')
Clearance Clearance_1 [All] p0: scope1count=1 scope1_0_kind=Board scope1_0_value=Board scope2count=1 scope2_0_kind=Board scope2_0_value=Board commentlength=0 gap=15
Clearance [All] p0: scope1count=1 scope1_0_kind=Board scope1_0_value=Board scope2count=1 scope2_0_kind=Board scope2_0_value=Board commentlength=0 gap=7.87
Clearance Clearance_FiducialMark [All] p0 off: scope1count=1 scope1_0_kind=Board scope1_0_value=Board scope2count=1 scope2_0_kind=Board scope2_0_value=Board commentlength=81 gap=0 // Protel DXP Scope 2 Expression Was: IsPad and InComponentClass('FiducialMark')
Clearance Clearance_Poly [All] p0 off: scope1count=1 scope1_0_kind=Board scope1_0_value=Board scope2count=1 scope2_0_kind=Board scope2_0_value=Board commentlength=48 gap=25 // Protel DXP Scope 1 Expression Was: InPolygon
Clearance Clearance_Keepouts [All] p0 off: scope1count=1 scope1_0_kind=Board scope1_0_value=Board scope2count=1 scope2_0_kind=Board scope2_0_value=Board commentlength=99 gap=0 // Protel DXP Scope 2 Expression Was: ((IsTrack Or IsArc) And Not InPoly) And IsFree and IsKeepOut
Clearance Clearance_2 [WithinRoom('Copper to PMIC IC')] p1: gap=5 ignorepadtopadclearanceinfootprint=FALSE except(0: Arc-Arc Arc-SMDPad Arc-Hole Track-Hole SMDPad-Hole THPad-Hole Via-Hole Fill-Hole Poly-Hole Region-Hole Text-Hole; 4: Arc-Track Track-Track; 4.5: Track-Via; 10: SMDPad-SMDPad)
Clearance Clearance_1 [All] p2: gap=15 ignorepadtopadclearanceinfootprint=FALSE except(0: Arc-SMDPad Arc-Hole Track-Hole SMDPad-Hole THPad-Hole Via-Hole Fill-Hole Poly-Hole Region-Hole Text-Hole; 5: Track-SMDPad; 5.6: Track-Region; 5.9: Via-Via; 6: Arc-Arc Arc-Track Arc-THPad Arc-Via Arc-Region Track-Track Track-THPad Track-Via SMDPad-SMDPad SMDPad-THPad SMDPad-Via SMDPad-Fill SMDPad-Poly THPad-THPad THPad-Via Via-Fill Via-Poly; 8: SMDPad-Region; 10: THPad-Fill THPad-Poly)
Clearance Clearance_Keepouts [((IsTrack Or IsArc) And Not InPoly) And IsFree and IsKeepOut vs ((IsTrack Or IsArc) And Not InPoly) And IsFree and IsKeepOut] p3: gap=0 ignorepadtopadclearanceinfootprint=FALSE
Clearance Clearance_Poly [InPolygon] p4: gap=25 ignorepadtopadclearanceinfootprint=FALSE except(0: Arc-Hole Track-Hole SMDPad-Hole THPad-Hole Via-Hole Fill-Hole Poly-Hole Region-Hole Text-Hole)
Clearance Clearance_FiducialMark [IsKeepOut and InComponentClass('FiducialMark') vs IsPad and InComponentClass('FiducialMark')] p5: gap=0 ignorepadtopadclearanceinfootprint=FALSE
Clearance [All] p6: gap=7.87 ignorepadtopadclearanceinfootprint=FALSE except(0: Arc-Hole Track-Hole SMDPad-Hole THPad-Hole Via-Hole Fill-Hole Poly-Hole Region-Hole Text-Hole)
ComponentClearance "Comp_Clr_J18 and J20" [All] p0: scope1count=1 scope1_0_kind=Component scope1_0_value=J18 scope2count=1 scope2_0_kind=Component scope2_0_value=J20 commentlength=0 gap=0 collisioncheckmode=3
ComponentClearance ComponentClearance_SMTtosmt [All] p0 off: scope1count=1 scope1_0_kind=Board scope1_0_value=Board scope2count=1 scope2_0_kind=Board scope2_0_value=Board commentlength=53 gap=10 collisioncheckmode=3 // Protel DXP Scope 2 Expression Was: IsSMTComponent
ComponentClearance [All] p0: scope1count=1 scope1_0_kind=Board scope1_0_value=Board scope2count=1 scope2_0_kind=Board scope2_0_value=Board commentlength=0 gap=10 collisioncheckmode=3
ComponentClearance ComponentClearance_THtoTH [All] p0 off: scope1count=1 scope1_0_kind=Board scope1_0_value=Board scope2count=1 scope2_0_kind=Board scope2_0_value=Board commentlength=54 gap=10 collisioncheckmode=3 // Protel DXP Scope 2 Expression Was: IsThruComponent
ComponentClearance ComponentClearance_THtoSMT [All] p0 off: scope1count=1 scope1_0_kind=Board scope1_0_value=Board scope2count=1 scope2_0_kind=Board scope2_0_value=Board commentlength=53 gap=10 collisioncheckmode=3 // Protel DXP Scope 2 Expression Was: IsSMTComponent
ComponentClearance ComponentClearance_SmallPassives [All] p0 off: scope1count=1 scope1_0_kind=Board scope1_0_value=Board scope2count=1 scope2_0_kind=Board scope2_0_value=Board commentlength=508 gap=20 collisioncheckmode=3 // Protel DXP Scope 2 Expression Was: HasFootprint('0201*') or HasFootprint('0402*') or HasFootprint('0508') or HasFootprint('0603*') or HasFootprint('0612') or HasFootprint('0805*') or HasFootprint('0815*') or HasFootprint('0830*') or HasFootprint('1206*') or HasFootprint('1210*') or HasFootprint('1808*') or HasFootprint('1812*') or HasFootprint('1825*') or HasFootprint('2010*') or HasFootprint('2220*') or HasFootprint('2225*') or HasFootprint('2512*') or HasFootprint('2728*') or HasFootprint('3518*')
ComponentClearance ComponentClearance_MountingHoles [All] p0: scope1count=1 scope1_0_kind=ComponentClass scope1_0_value="Mounting Holes" scope2count=1 scope2_0_kind=Board scope2_0_value=Board commentlength=0 gap=50 collisioncheckmode=3
ComponentClearance ComponentClearance_ScrewToNut [All] p0 off: scope1count=1 scope1_0_kind=Board scope1_0_value=Board scope2count=1 scope2_0_kind=Board scope2_0_value=Board commentlength=71 gap=5 collisioncheckmode=3 // Protel DXP Scope 2 Expression Was: (HasFootprint('Keystone_1902C'))
ComponentClearance ComponentClearance_Logo [All] p0: scope1count=1 scope1_0_kind=ComponentClass scope1_0_value=Logo scope2count=1 scope2_0_kind=Board scope2_0_value=Board commentlength=0 gap=5 collisioncheckmode=3
ComponentClearance ComponentClearance_Shunt [All] p0: scope1count=1 scope1_0_kind=ComponentClass scope1_0_value=Header scope2count=1 scope2_0_kind=ComponentClass scope2_0_value=Shunt commentlength=0 gap=0 collisioncheckmode=3
ComponentClearance ComponentClearance_MountingHoles_FiducialMarks [All] p0: scope1count=1 scope1_0_kind=ComponentClass scope1_0_value="Mounting Holes" scope2count=1 scope2_0_kind=ComponentClass scope2_0_value=FiducialMark commentlength=0 gap=10 collisioncheckmode=3
ComponentClearance Comp_Clr_J19 [All] p0: scope1count=1 scope1_0_kind=Component scope1_0_value=Logo3 scope2count=1 scope2_0_kind=Component scope2_0_value=J19 commentlength=0 gap=0 collisioncheckmode=3
ComponentClearance "Comp_Clr_349 to 347" [All] p0: scope1count=1 scope1_0_kind=Component scope1_0_value=R349 scope2count=1 scope2_0_kind=Component scope2_0_value=R347 commentlength=0 gap=0 collisioncheckmode=3
ComponentClearance "Comp_Clr_350 to 351" [All] p0: scope1count=1 scope1_0_kind=Component scope1_0_value=R350 scope2count=1 scope2_0_kind=Component scope2_0_value=R351 commentlength=0 gap=0 collisioncheckmode=3
ComponentClearance "Comp_Clr_357 to 358" [All] p0: scope1count=1 scope1_0_kind=Component scope1_0_value=R357 scope2count=1 scope2_0_kind=Component scope2_0_value=R358 commentlength=0 gap=0 collisioncheckmode=3
ComponentClearance "Comp_Clr_360 to 359" [All] p0: scope1count=1 scope1_0_kind=Component scope1_0_value=R359 scope2count=1 scope2_0_kind=Component scope2_0_value=R360 commentlength=0 gap=0 collisioncheckmode=3
ComponentClearance "Comp_Clr_361 to 362" [All] p0: scope1count=1 scope1_0_kind=Component scope1_0_value=R361 scope2count=1 scope2_0_kind=Component scope2_0_value=R362 commentlength=0 gap=0 collisioncheckmode=3
ComponentClearance "Comp_Clr_Log1 to logo3" [All] p0: scope1count=1 scope1_0_kind=Component scope1_0_value=Logo1 scope2count=1 scope2_0_kind=Component scope2_0_value=Logo3 commentlength=0 gap=0 collisioncheckmode=3
ComponentClearance "Comp_Clr_Log3 to logo2" [All] p0: scope1count=1 scope1_0_kind=Component scope1_0_value=Logo3 scope2count=1 scope2_0_kind=Component scope2_0_value=Logo2 commentlength=0 gap=0 collisioncheckmode=3
ComponentClearance "Comp_Clr_Log3 to logo2" [InComponent('Logo3') vs InComponent('Logo2')] p1: gap=0 collisioncheckmode=3 verticalgap=0 showdistances=FALSE
ComponentClearance "Comp_Clr_Log1 to logo3" [InComponent('Logo1') vs InComponent('Logo3')] p2: gap=0 collisioncheckmode=3 verticalgap=0 showdistances=FALSE
ComponentClearance "Comp_Clr_361 to 362" [InComponent('R361') vs InComponent('R362')] p3: gap=0 collisioncheckmode=3 verticalgap=0 showdistances=FALSE
ComponentClearance "Comp_Clr_360 to 359" [InComponent('R359') vs InComponent('R360')] p4: gap=0 collisioncheckmode=3 verticalgap=0 showdistances=FALSE
ComponentClearance "Comp_Clr_357 to 358" [InComponent('R357') vs InComponent('R358')] p5: gap=0 collisioncheckmode=3 verticalgap=0 showdistances=FALSE
ComponentClearance "Comp_Clr_350 to 351" [InComponent('R350') vs InComponent('R351')] p6: gap=0 collisioncheckmode=3 verticalgap=0 showdistances=FALSE
ComponentClearance "Comp_Clr_349 to 347" [InComponent('R349') vs InComponent('R347')] p7: gap=0 collisioncheckmode=3 verticalgap=0 showdistances=FALSE
ComponentClearance Comp_Clr_J19 [InComponent('Logo3') vs InComponent('J19')] p8: gap=0 collisioncheckmode=3 verticalgap=0 showdistances=FALSE
ComponentClearance "Comp_Clr_J18 and J20" [InComponent('J18') vs InComponent('J20')] p9: gap=0 collisioncheckmode=3 verticalgap=0 showdistances=FALSE
ComponentClearance ComponentClearance_SMTtosmt [IsSMTComponent vs IsSMTComponent] p10: gap=10 collisioncheckmode=3 verticalgap=10 showdistances=FALSE
ComponentClearance ComponentClearance_MountingHoles_FiducialMarks [InComponentClass('Mounting Holes') vs InComponentClass('FiducialMark')] p11: gap=10 collisioncheckmode=3 verticalgap=15 showdistances=FALSE
ComponentClearance ComponentClearance_Shunt [InComponentClass('Header') vs InComponentClass('Shunt')] p12: gap=0 collisioncheckmode=3 verticalgap=0 showdistances=FALSE
ComponentClearance ComponentClearance_Logo [InComponentClass('Logo')] p13: gap=5 collisioncheckmode=3 verticalgap=5 showdistances=FALSE
ComponentClearance ComponentClearance_ScrewToNut [(HasFootprint('NY PMS 440 0025 PH')) vs (HasFootprint('Keystone_1902C'))] p14: gap=5 collisioncheckmode=3 verticalgap=10 showdistances=FALSE
ComponentClearance ComponentClearance_MountingHoles [InComponentClass('Mounting Holes')] p15: gap=50 collisioncheckmode=3 verticalgap=100000 showdistances=FALSE
ComponentClearance ComponentClearance_SmallPassives [HasFootprint('0201*') or HasFootprint('0402*') or HasFootprint('0508') or HasFootprint('0603*') or HasFootprint('0612') or HasFootprint('0805*') or HasFootprint('0815*') or HasFootprint('0830*') or HasFootprint('1206*') or HasFootprint('1210*') or HasFootprint('1808*') or HasFootprint('1812*') or HasFootprint('1825*') or HasFootprint('2010*') or HasFootprint('2220*') or HasFootprint('2225*') or HasFootprint('2512*') or HasFootprint('2728*') or HasFootprint('3518*') vs HasFootprint('0201*') or HasFootprint('0402*') or HasFootprint('0508') or HasFootprint('0603*') or HasFootprint('0612') or HasFootprint('0805*') or HasFootprint('0815*') or HasFootprint('0830*') or HasFootprint('1206*') or HasFootprint('1210*') or HasFootprint('1808*') or HasFootprint('1812*') or HasFootprint('1825*') or HasFootprint('2010*') or HasFootprint('2220*') or HasFootprint('2225*') or HasFootprint('2512*') or HasFootprint('2728*') or HasFootprint('3518*')] p16: gap=20 collisioncheckmode=3 verticalgap=20 showdistances=FALSE
ComponentClearance ComponentClearance_THtoSMT [IsThruComponent vs IsSMTComponent] p17: gap=10 collisioncheckmode=3 verticalgap=10 showdistances=FALSE
ComponentClearance ComponentClearance_THtoTH [IsThruComponent vs IsThruComponent] p18: gap=10 collisioncheckmode=3 verticalgap=10 showdistances=FALSE
ComponentClearance [All] p19: gap=10 collisioncheckmode=3 verticalgap=10 showdistances=TRUE
DiffPairsRouting 90OHM [All] p0 off: scope1count=1 scope1_0_kind=Board scope1_0_value=Board scope2count=1 scope2_0_kind=Board scope2_0_value=Board commentlength=71 // Protel DXP Scope 1 Expression Was: InDifferentialPairClass('90ohm')
DiffPairsRouting 100OHM [All] p0 off: scope1count=1 scope1_0_kind=Board scope1_0_value=Board scope2count=1 scope2_0_kind=Board scope2_0_value=Board commentlength=72 // Protel DXP Scope 1 Expression Was: InDifferentialPairClass('100ohm')
DiffPairsRouting 90OHM [InDifferentialPairClass('90ohm')] p1: maxlimit=6.01 minlimit=6.01 mostfreqgap=6.01 toplayer_minwidth=4.99 toplayer_maxwidth=4.99 toplayer_prefwidth=4.99 midlayer1_mingap=0 midlayer1_maxgap=0 midlayer1_prefgap=0 midlayer1_minwidth=0 midlayer1_maxwidth=0 midlayer1_prefwidth=0 midlayer2_minwidth=3.99 midlayer2_maxwidth=3.99 midlayer2_prefwidth=3.99 midlayer3_mingap=0 midlayer3_maxgap=0 midlayer3_prefgap=0 midlayer3_minwidth=0 midlayer3_maxwidth=0 midlayer3_prefwidth=0 midlayer4_minwidth=3.99 midlayer4_maxwidth=3.99 midlayer4_prefwidth=3.99 midlayer5_minwidth=3.99 midlayer5_maxwidth=3.99 midlayer5_prefwidth=3.99 midlayer6_mingap=0 midlayer6_maxgap=0 midlayer6_prefgap=0 midlayer6_minwidth=0 midlayer6_maxwidth=0 midlayer6_prefwidth=0 midlayer7_minwidth=3.99 midlayer7_maxwidth=3.99 midlayer7_prefwidth=3.99 midlayer8_mingap=0 midlayer8_maxgap=0 midlayer8_prefgap=0 midlayer8_minwidth=0 midlayer8_maxwidth=0 midlayer8_prefwidth=0 bottomlayer_minwidth=4.99 bottomlayer_maxwidth=4.99 bottomlayer_prefwidth=4.99 maxuncoupledlength=500
DiffPairsRouting 100OHM [InDifferentialPairClass('100ohm')] p2: maxlimit=11.99 minlimit=8.99 mostfreqgap=9.99 toplayer_maxgap=8.99 toplayer_prefgap=8.99 toplayer_minwidth=5.01 toplayer_maxwidth=5.01 toplayer_prefwidth=5.01 midlayer1_mingap=0 midlayer1_maxgap=0 midlayer1_prefgap=0 midlayer1_minwidth=0 midlayer1_maxwidth=0 midlayer1_prefwidth=0 midlayer2_mingap=11.99 midlayer2_prefgap=11.99 midlayer2_minwidth=4.01 midlayer2_maxwidth=4.01 midlayer2_prefwidth=4.01 midlayer3_mingap=0 midlayer3_maxgap=0 midlayer3_prefgap=0 midlayer3_minwidth=0 midlayer3_maxwidth=0 midlayer3_prefwidth=0 midlayer4_mingap=9.99 midlayer4_maxgap=9.99 midlayer4_minwidth=4.01 midlayer4_maxwidth=4.01 midlayer4_prefwidth=4.01 midlayer5_mingap=9.99 midlayer5_maxgap=9.99 midlayer5_minwidth=4.01 midlayer5_maxwidth=4.01 midlayer5_prefwidth=4.01 midlayer6_mingap=0 midlayer6_maxgap=0 midlayer6_prefgap=0 midlayer6_minwidth=0 midlayer6_maxwidth=0 midlayer6_prefwidth=0 midlayer7_mingap=11.99 midlayer7_prefgap=11.99 midlayer7_minwidth=4.01 midlayer7_maxwidth=11.99 midlayer7_prefwidth=4.01 midlayer8_mingap=0 midlayer8_maxgap=0 midlayer8_prefgap=0 midlayer8_minwidth=0 midlayer8_maxwidth=0 midlayer8_prefwidth=0 bottomlayer_maxgap=8.99 bottomlayer_prefgap=8.99 bottomlayer_minwidth=5.01 bottomlayer_maxwidth=5.01 bottomlayer_prefwidth=5.01 maxuncoupledlength=1000
FabricationTestPointUsage TestPointUsage [All] p0: scope1count=1 scope1_0_kind=Board scope1_0_value=Board scope2count=1 scope2_0_kind=Board scope2_0_value=Board commentlength=0 valid=2 allowmultiple=FALSE
FabricationTestPointUsage TestPointUsage [All] p1: valid=2 allowmultiple=FALSE
FabricationTestpoint Testpoint [All] p0: scope1count=1 scope1_0_kind=Board scope1_0_value=Board scope2count=1 scope2_0_kind=Board scope2_0_value=Board commentlength=0 side=3 testpointundercomponent=TRUE minsize=40 maxsize=100 preferedsize=60 minholesize=0 maxholesize=40 preferedholesize=32 testpointgrid=1
FabricationTestpoint Testpoint [All] p1: side=3 testpointundercomponent=TRUE minsize=40 maxsize=100 preferedsize=60 minholesize=0 maxholesize=40 preferedholesize=32 testpointgrid=1 allowsidetop=TRUE allowsidebottom=TRUE usegrid=TRUE gridtolerance=0.01
FanoutControl Fanout_Small [All] p0 off: scope1count=1 scope1_0_kind=Board scope1_0_value=Board scope2count=1 scope2_0_kind=Board scope2_0_value=Board commentlength=84 // Protel DXP Scope 1 Expression Was: (CompPinCount < 5)   Fanout_Small (Default Rule)
FanoutControl Fanout_Default [All] p0: scope1count=1 scope1_0_kind=Board scope1_0_value=Board scope2count=1 scope2_0_kind=Board scope2_0_value=Board commentlength=30 // Fanout_Default (Default Rule)
FanoutControl Fanout_SOIC [All] p0 off: scope1count=1 scope1_0_kind=Board scope1_0_value=Board scope2count=1 scope2_0_kind=Board scope2_0_value=Board commentlength=71 // Protel DXP Scope 1 Expression Was: IsSOIC   Fanout_SOIC (Default Rule)
FanoutControl Fanout_BGA [All] p0 off: scope1count=1 scope1_0_kind=Board scope1_0_value=Board scope2count=1 scope2_0_kind=Board scope2_0_value=Board commentlength=69 // Protel DXP Scope 1 Expression Was: IsBGA   Fanout_BGA (Default Rule)
FanoutControl Fanout_LCC [All] p0 off: scope1count=1 scope1_0_kind=Board scope1_0_value=Board scope2count=1 scope2_0_kind=Board scope2_0_value=Board commentlength=69 // Protel DXP Scope 1 Expression Was: IsLCC   Fanout_LCC (Default Rule)
FanoutControl Fanout_LCC [IsLCC] p1: bgadir=Out bgaviamode=Centered fanoutstyle=Auto fanoutdirection=Alternating viagrid=1 // Fanout_LCC (Default Rule)
FanoutControl Fanout_BGA [IsBGA] p2: bgadir=Out bgaviamode=Centered fanoutstyle=Auto fanoutdirection=Alternating viagrid=1 // Fanout_BGA (Default Rule)
FanoutControl Fanout_Default [All] p4: bgadir=Out bgaviamode=Centered fanoutstyle=Auto fanoutdirection=Alternating viagrid=1 // Fanout_Default (Default Rule)
FanoutControl Fanout_Small [(CompPinCount < 5)] p5: bgadir=Out bgaviamode=Centered fanoutstyle=Auto fanoutdirection=OutThenIn viagrid=1 // Fanout_Small (Default Rule)
Height [All] p0: scope1count=1 scope1_0_kind=Board scope1_0_value=Board scope2count=1 scope2_0_kind=Board scope2_0_value=Board commentlength=0
HoleSize [All] p0: scope1count=1 scope1_0_kind=Board scope1_0_value=Board scope2count=1 scope2_0_kind=Board scope2_0_value=Board commentlength=0 absolutevalues=TRUE maxlimit=251 minlimit=7.87 maxpercent=80.000 minpercent=20.000
HoleSize [All] p1: absolutevalues=TRUE maxlimit=251 minlimit=7.87 maxpercent=80.000 minpercent=20.000
HoleToHoleClearance [All] p0: scope1count=1 scope1_0_kind=Board scope1_0_value=Board scope2count=1 scope2_0_kind=Board scope2_0_value=Board commentlength=0
HoleToHoleClearance [All] p1: gap=8 allowstackedmicrovias=TRUE
LayerPairs [All] p0: scope1count=1 scope1_0_kind=Board scope1_0_value=Board scope2count=1 scope2_0_kind=Board scope2_0_value=Board commentlength=0 enforce=TRUE
MatchedLengths LVDS_phase [All] p0 off: scope1count=1 scope1_0_kind=Board scope1_0_value=Board scope2count=1 scope2_0_kind=Board scope2_0_value=Board commentlength=72 tolerance=10 amplitude=200 gap=20 style=90-Degree // Protel DXP Scope 1 Expression Was: InDifferentialPairClass('100ohm')
MatchedLengths LVDS [All] p0 off: scope1count=1 scope1_0_kind=Board scope1_0_value=Board scope2count=1 scope2_0_kind=Board scope2_0_value=Board commentlength=72 tolerance=50 amplitude=200 gap=20 style=90-Degree // Protel DXP Scope 1 Expression Was: InDifferentialPairClass('100ohm')
MatchedLengths Radar [All] p0: scope1count=1 scope1_0_kind=NetClass scope1_0_value=Radar scope2count=1 scope2_0_kind=Board scope2_0_value=Board commentlength=0 tolerance=150 amplitude=200 gap=20 style=90-Degree
MatchedLengths SPI [All] p0: scope1count=1 scope1_0_kind=NetClass scope1_0_value=SPI scope2count=1 scope2_0_kind=Board scope2_0_value=Board commentlength=0 tolerance=200 amplitude=200 gap=20 style=90-Degree
MatchedLengths LVDS_phase [InDifferentialPairClass('100ohm')] p1: tolerance=10 checknetsindiffpair=TRUE checkdiffpairvsdiffpair=FALSE checkxsignals=FALSE checkothers=FALSE
MatchedLengths LVDS [InDifferentialPairClass('100ohm')] p2: tolerance=50 checknetsindiffpair=FALSE checkdiffpairvsdiffpair=TRUE checkxsignals=TRUE checkothers=TRUE
MatchedLengths Radar [InNetClass('Radar')] p3: tolerance=150 checknetsindiffpair=FALSE checkdiffpairvsdiffpair=TRUE checkxsignals=TRUE checkothers=TRUE
MatchedLengths SPI [InNetClass('SPI')] p4: tolerance=200 checknetsindiffpair=FALSE checkdiffpairvsdiffpair=TRUE checkxsignals=TRUE checkothers=TRUE
MinimumAnnularRing [All] p0: scope1count=1 scope1_0_kind=Board scope1_0_value=Board scope2count=1 scope2_0_kind=Board scope2_0_value=Board commentlength=0 minimumring=5.1
MinimumAnnularRing MinimumAnnularRing_ThermalPadVias [All] p0 off: scope1count=1 scope1_0_kind=Board scope1_0_value=Board scope2count=1 scope2_0_kind=Board scope2_0_value=Board commentlength=63 minimumring=3.9 // Protel DXP Scope 1 Expression Was: IsVia and InAnyComponent
MinimumAnnularRing MinimumAnnularRing_ThermalPadVias [IsVia and InAnyComponent] p1: minimumring=3.9
MinimumAnnularRing [All] p2: minimumring=5.1
MinimumSolderMaskSliver [All] p0: scope1count=1 scope1_0_kind=Board scope1_0_value=Board scope2count=1 scope2_0_kind=Board scope2_0_value=Board commentlength=0
MinimumSolderMaskSliver MinimumSolderMaskSliver_Logo [All] p0: scope1count=1 scope1_0_kind=ComponentClass scope1_0_value=Logo scope2count=1 scope2_0_kind=ComponentClass scope2_0_value=Logo commentlength=0
MinimumSolderMaskSliver MinimumSolderMaskSliver_Logo [InComponentClass('Logo') vs InComponentClass('Logo')] p1: minsoldermaskwidth=0.7
MinimumSolderMaskSliver [All] p2: minsoldermaskwidth=3.5
NetAntennae [All] p0: scope1count=1 scope1_0_kind=Board scope1_0_value=Board scope2count=1 scope2_0_kind=Board scope2_0_value=Board commentlength=0
NetAntennae [All] p1: netantennaetolerance=4
PasteMaskExpansion [All] p0: scope1count=1 scope1_0_kind=Board scope1_0_value=Board scope2count=1 scope2_0_kind=Board scope2_0_value=Board commentlength=0 expansion=0
PlaneClearance [All] p0: scope1count=1 scope1_0_kind=Board scope1_0_value=Board scope2count=1 scope2_0_kind=Board scope2_0_value=Board commentlength=0 clearance=20
PlaneConnect [All] p0: scope1count=1 scope1_0_kind=Board scope1_0_value=Board scope2count=1 scope2_0_kind=Board scope2_0_value=Board commentlength=0 planeconnectstyle=Relief reliefexpansion=10 reliefentries=4 reliefconductorwidth=10 reliefairgap=10
PlaneConnect [All] p1: planeconnectstyle=Relief reliefexpansion=10 reliefentries=4 reliefconductorwidth=10 reliefairgap=10
PolygonConnect [All] p0: scope1count=1 scope1_0_kind=Board scope1_0_value=Board scope2count=1 scope2_0_kind=Board scope2_0_value=Board commentlength=0 connectstyle=Direct reliefconductorwidth=10 reliefentries=4 polygonreliefangle="90 Angle"
PolygonConnect [All] p1: connectstyle=Direct reliefconductorwidth=10 reliefentries=4 polygonreliefangle="90 Angle" airgapwidth=10
RoutingCorners [All] p0: scope1count=1 scope1_0_kind=Board scope1_0_value=Board scope2count=1 scope2_0_kind=Board scope2_0_value=Board commentlength=0 cornerstyle=45-Degree minsetback=100 maxsetback=100
RoutingLayers [All] p0: scope1count=1 scope1_0_kind=Board scope1_0_value=Board scope2count=1 scope2_0_kind=Board scope2_0_value=Board commentlength=0 top layer=Automatic mid layer 1=Automatic mid layer 2=Automatic mid layer 3=Automatic mid layer 4=Automatic mid layer 5=Automatic mid layer 6=Automatic mid layer 7=Automatic mid layer 8=Automatic bottom layer=Automatic
RoutingPriority [All] p0: scope1count=1 scope1_0_kind=Board scope1_0_value=Board scope2count=1 scope2_0_kind=Board scope2_0_value=Board commentlength=0
RoutingTopology [All] p0: scope1count=1 scope1_0_kind=Board scope1_0_value=Board scope2count=1 scope2_0_kind=Board scope2_0_value=Board commentlength=0 topology=Shortest
RoutingVias [All] p0: scope1count=1 scope1_0_kind=Board scope1_0_value=Board scope2count=1 scope2_0_kind=Board scope2_0_value=Board commentlength=0 holewidth=12.2 width=22.4 viastyle="Through Hole" minholewidth=7.87 minwidth=15.75 maxholewidth=12.2 maxwidth=22.4
RoutingVias ThermalPadVias [All] p0 off: scope1count=1 scope1_0_kind=Board scope1_0_value=Board scope2count=1 scope2_0_kind=Board scope2_0_value=Board commentlength=63 holewidth=12.2 width=22.4 viastyle="Through Hole" minholewidth=7.87 minwidth=15.75 maxholewidth=12.2 maxwidth=22.4 // Protel DXP Scope 1 Expression Was: IsVia and InAnyComponent
RoutingVias ThermalPadVias [IsVia and InAnyComponent] p1: holewidth=12.2 width=22.4 viastyle="Through Hole" minholewidth=7.87 minwidth=15.75 maxholewidth=12.2 maxwidth=22.4
RoutingVias [All] p2: holewidth=12.2 width=22.4 viastyle="Through Hole" minholewidth=7.87 minwidth=15.75 maxholewidth=12.2 maxwidth=22.4
ShortCircuit [All] p0: scope1count=1 scope1_0_kind=Board scope1_0_value=Board scope2count=1 scope2_0_kind=Board scope2_0_value=Board commentlength=0 allowed=FALSE
SilkToBoardRegionClearance [All] p0 off: scope1count=1 scope1_0_kind=Board scope1_0_value=Board scope2count=1 scope2_0_kind=Board scope2_0_value=Board commentlength=130 // Protel DXP Scope 1 Expression Was: Not ((IsComment or IsDesignator) And (Hide <> 'False')) and not InRegion(1000,500,4000,800)
SilkToBoardRegionClearance [Not ((IsComment or IsDesignator) And (Hide <> 'False')) and not InRegion(1000,500,4000,800)] p1:
SilkToSilkClearance [All] p0: scope1count=1 scope1_0_kind=Board scope1_0_value=Board scope2count=1 scope2_0_kind=Board scope2_0_value=Board commentlength=0
SilkToSilkClearance SilkToSilkClearance_Pb-FreeLogo [All] p0 off: scope1count=1 scope1_0_kind=Board scope1_0_value=Board scope2count=1 scope2_0_kind=Board scope2_0_value=Board commentlength=120 // Protel DXP Scope 2 Expression Was: (HasFootprint('Pb-Free_Overlay_Medium') OR HasFootprint('Pb-Free_Overlay_Small'))
SilkToSilkClearance SilkToSilkClearance_Pb-FreeLogo [(HasFootprint('Pb-Free_Overlay_Medium') OR HasFootprint('Pb-Free_Overlay_Small')) vs (HasFootprint('Pb-Free_Overlay_Medium') OR HasFootprint('Pb-Free_Overlay_Small'))] p1: silktosilkclearance=0
SilkToSilkClearance [All] p2: silktosilkclearance=3
SilkToSolderMaskClearance "Silk to Solder Mask Opening" [All] p0: scope1count=1 scope1_0_kind=Board scope1_0_value=Board scope2count=1 scope2_0_kind=Board scope2_0_value=Board commentlength=0
SilkToSolderMaskClearance SilkToComponentPadClearance [All] p0 off: scope1count=1 scope1_0_kind=Board scope1_0_value=Board scope2count=1 scope2_0_kind=Board scope2_0_value=Board commentlength=87 // Protel DXP Scope 1 Expression Was: (IsPad or IsFill or IsRegion) and InAnycomponent
SilkToSolderMaskClearance SilkToComponentPadClearance [(IsPad or IsFill or IsRegion) and InAnycomponent] p1: minsilkscreentomaskgap=3 clearancetoexposedcopper=TRUE
SilkToSolderMaskClearance "Silk to Solder Mask Opening" [All] p2: minsilkscreentomaskgap=4 clearancetoexposedcopper=FALSE
SolderMaskExpansion [All] p0: scope1count=1 scope1_0_kind=Board scope1_0_value=Board scope2count=1 scope2_0_kind=Board scope2_0_value=Board commentlength=0 expansion=0
SolderMaskExpansion [All] p1: expansion=0
UnRoutedNet [All] p0: scope1count=1 scope1_0_kind=Board scope1_0_value=Board scope2count=1 scope2_0_kind=Board scope2_0_value=Board commentlength=0
UnpouredPolygon [All] p0: scope1count=1 scope1_0_kind=Board scope1_0_value=Board scope2count=1 scope2_0_kind=Board scope2_0_value=Board commentlength=0
Width pwr [All] p0: scope1count=1 scope1_0_kind=NetClass scope1_0_value=PWR scope2count=1 scope2_0_kind=Board scope2_0_value=Board commentlength=0 maxlimit=100 minlimit=6 preferedwidth=10
Width [All] p0: scope1count=1 scope1_0_kind=Board scope1_0_value=Board scope2count=1 scope2_0_kind=Board scope2_0_value=Board commentlength=0 maxlimit=100 minlimit=4 preferedwidth=6
Width pwr [InNetClass('PWR')] p1: maxlimit=100 minlimit=6 preferedwidth=10 checkconnectedcopper=TRUE
Width [All] p2: maxlimit=100 minlimit=4 preferedwidth=6 checkconnectedcopper=TRUE
13 further rules are at their usual default settings.

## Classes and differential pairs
net class SPI: 40PIN_CS1 40PIN_MISO1 40PIN_MOSI1 40PIN_SPI_CLK1 60PIN_CS1 60PIN_MISO1 60PIN_MOSI1 60PIN_SPICLK1 FTDI_CLK1 FTDI_CS1 FTDI_MISO1 FTDI_MOSI1 MUX_CS1 MUX_MISO1 MUX_MOSI1 MUX_SPI_CLK1 RADAR_SPI_CLK1 RADAR_SPI_CS1 RADAR_SPI_MISO1 RADAR_SPI_MOSI1 SPI_CLK1 SPI_CS1 SPI_MISO1 SPI_MOSI1
net class PWR: 5V_IN BOOST_3V3_IN BP_LP_3V3 BRD_3V3 CB_PMIC_1V0 CB_PMIC_1V2 CB_PMIC_1V8 FPWM1 FPWM2 FTDI_3V3 FTDI_VBUS FTDI_VCORE GND MCU_3V3 MCU_5V NetC1_2 NetC22_1 NetC74_1 NetC96_2 NetD1_1 NetF1_2 NetJ10_1 PMIC_1V0 PMIC_1V2 PMIC_1V8 PMIC_3V3 PMICVIO_3V3 UNREG_IN1 UNREG_IN2 VBOOST_5V VCC_3V3 VCC_XDS_3V3 VDDC_1 VLDO_3V3 VPP_1P7 WIDE_IN_5V_OP XDSET_1_VBUS
net class LVDS: RADAR_LVDS_0M RADAR_LVDS_0P RADAR_LVDS_1M RADAR_LVDS_1P RADAR_LVDS_2M RADAR_LVDS_2P RADAR_LVDS_3M RADAR_LVDS_3P RADAR_LVDS_CLKM RADAR_LVDS_CLKP RADAR_LVDS_FRCLKM RADAR_LVDS_FRCLKP RADAR_LVDS_VALIDM RADAR_LVDS_VALIDP
net class Radar: RADAR_DP0 RADAR_DP1 RADAR_DP2 RADAR_DP3 RADAR_DP4 RADAR_DP5 RADAR_DP6 RADAR_DP7 RADAR_DP8 RADAR_DP9 RADAR_DP10 RADAR_DP11 RADAR_DP12 RADAR_DP13 RADAR_DP14 RADAR_DP15
component class Label: LBL1
component class AssemblyNote: ZZ1 ZZ2 ZZ3 ZZ4 ZZ5
component class FiducialMark: FID1 FID2 FID3 FID4 FID5 FID6
component class PROC074A_EVM_Hardware: "CAUTION HOT SURFACE1" FID1 FID2 FID3 FID4 FID5 FID6 LBL1 Logo1 Logo2 Logo3 Logo4 ZZ1 ZZ2 ZZ3 ZZ4 ZZ5
component class Logo: Logo1
component class Header: J13 J14 J15 J16 J18 J19 J20 J27 J28 P1 P3 P4 P5 P6 P7
component class PROC074A_Analog_Mux_1A: C27 C72 C73 C92 C93 C94 R16 R17 R25 R26 R63 R66 R151 R203 R209 R250 R338 R339 U5 U10 U24 U25 U26 U27
component class PROC074A_Analog_Mux_1B: C95 C114 C115 C116 J14 J15 R18 R19 R23 R24 R62 R65 R68 R262 S1 U28 U33 U34 U35
component class PROC074A_BP_LP_RNR_Options: J16 R9 R13 R22 R69 R73 R247 R248 R249 R274 R275 R281 R283 R346 R347 R348 R349 R350 R351 R353 R354 R356 R357 R358 R359 R360 R361 R362 R398
component class PROC074A_CAN_Interface_LEDs: C5 C71 C74 C75 C76 C77 D5 D6 D7 D8 D9 D10 J2 L7 R10 R11 R12 R15 R31 R32 R33 R251 R252 R253 R254 R255 R256 U3 U12
component class PROC074A_CAN_Interface: C1 C2 C3 C4 C88 C119 C120 J1 P1 R1 R2 R3 R4 R5 R6 R7 R8 R260 R261 R395 R396 R397 U1 U2 U30
component class PROC074A_Current_Sensors: C6 C7 C8 C25 C26 R299 R301 R303 R304 R305 R306 R307 R308 R310 R311 R314 R316 R317 R319 R320 R321 R322 R323 R324 R325 R327 R328 R330 R331 R332 U11 U20 U21 U22 U23
component class PROC074A_FTDI_Interface_PWR: C55 C62 C63 C64 C65 C66 C67 C68 C69 C70 J12 J13 R181 R185 R186 R187 R193 R219 R220 R221 R222 R223 R225 R226 R227 R228 R290 U14 U16 U17
component class PROC074A_FTDI_Interface: C51 C52 C53 C54 C56 C57 C58 C59 C60 C61 D4 L5 L6 R43 R182 R183 R184 R188 R189 R190 R191 R192 R194 R195 R196 R197 R198 R199 R200 R201 R202 R204 R205 R206 R207 R208 R210 R211 R212 R213 R214 R215 R216 R217 R218 U15 Y2
component class PROC074A_HD_Conn_JTAG_HDR: C117 J3 J4 J17 J18 J19 J20 R14 R34 R35 R36 R37 R38 R39 R40 R41 R42 R44 R45 R46 R52 R53 R232 R233 R234 R273 R294 R295 R296 R297 R298 U36
component class PROC074A_HD_Connector_DCA: J9 J10 R20 R21 R27 R28 R29 R30 R54 R96 R144 R145 R146 R229 R230 R231 R235 R236 R237 R238 R239 R240 R241 R242 R243 R244 R245 R246 R268 R269 R270
component class PROC074A_LP8752J_PMIC: C9 C10 C11 C12 C13 C14 C15 C16 C17 C18 C19 C20 C21 L1 L2 L3 L4 R97 R98 R99 R100 R101 R102 R103 R104 R105 R106 R107 R108 R109 R110 R111 R112 R286 R287 R288 R289 R399 R400 R401 R402 U4
component class PROC074A_LP_Connector: J5 J6 J7 J8 R55 R56 R57 R58 R59 R60 R61 R64 R67 R70 R72 R75 R76 R77 R78 R79 R81 R82 R85 R86 R88 R89 R90 R91 R92 R93 R94 R95 R122 R224 R276 R393 R394
component class PROC074A_PWR_INPUT_REG: C31 C78 C79 C80 C81 C82 C83 C84 C85 C86 C87 C89 C90 C91 C96 C97 C98 C99 C100 C101 C102 C103 C104 C105 C106 C107 C108 C109 C110 C111 C112 C113 D11 D14 J27 J28 L8 L9 R49 R50 R113 R115 R271 R272 R291 R293 R309 R312 R313 R315 R318 R326 R329 R363 R364 R367 R368 R369 R370 R403 R404 TP1 U13 U29 U31 U32
component class PROC074A_PWR_RST_LEDs: C22 C23 C24 D1 DS1 DS2 DS3 DS4 F1 FB1 FB2 P2 P3 P7 Q1 Q2 R51 R71 R74 R80 R114 R116 R117 R118 R119 R120 R121 R123 R124 R125 R126 R127 R128 R129 R130 SW1 SW2
component class PROC074A_SOP_Selection: P4 P5 P6 R131 R132 R133 R134 R135 R136 R137 R138 R139 R140 R141 R142 R143
component class PROC074A_Temp_Sensor: C49 C50 R171 R172 R173 R174 R175 R176 R177 R178 R179 R180 U18 U19
component class PROC074A_XDS110_Interface_1A: C28 C29 C30 C32 C33 C34 C35 C36 C37 C38 C39 C40 C41 C42 J11 R147 R148 R149 R150 R152 R153 R154 R155 R156 U6 U7
component class PROC074A_XDS110_Interface_1B: C43 C44 C45 C46 C47 C48 R47 R48 R157 R158 R159 R160 R161 R162 R163 R164 R165 R166 R167 R168 R169 R170 U8 U9 Y1
differential pair D_XDSET_1_D: +XDSET_1_DM -XDSET_1_DP
differential pair D_USBD: +USBDM -USBDP
differential pair D_RADAR_LVDS_VALID: +RADAR_LVDS_VALIDM -RADAR_LVDS_VALIDP
differential pair D_RADAR_LVDS_FRCLK: +RADAR_LVDS_FRCLKM -RADAR_LVDS_FRCLKP
differential pair D_RADAR_LVDS_CLK: +RADAR_LVDS_CLKM -RADAR_LVDS_CLKP
differential pair D_RADAR_LVDS_3: +RADAR_LVDS_3M -RADAR_LVDS_3P
differential pair D_RADAR_LVDS_2: +RADAR_LVDS_2M -RADAR_LVDS_2P
differential pair D_RADAR_LVDS_1: +RADAR_LVDS_1M -RADAR_LVDS_1P
differential pair " ": +RADAR_LVDS_0M -RADAR_LVDS_0P

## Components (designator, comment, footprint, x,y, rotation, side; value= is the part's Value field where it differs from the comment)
C1 "C0402C104K8RACTU" 0402L 1495,1880 r90 bottom
C2 "C0402C104K8RACTU" 0402L 1305,1990 r0 top
C3 "C1005X7R1H472K050BA" 0402L 2387.09,1612.3 r0 top
C4 "C0402C104K8RACTU" 0402 2225,1885 r180 top
C5 "C1005X7R1H472K050BA" 0402 1536.81,1628.78 r270 bottom
C6 "CGA2B3X7R1H104K050BB" 0402L 2275.32,1605 r180 bottom
C7 "CGA2B3X7R1H104K050BB" 0402L 1642.37,2634.06 r90 top
C8 "CGA2B3X7R1H104K050BB" 0402L 1984.37,1514.06 r180 bottom
C9 "GCM21BR71A106KE22L" 0805_HV 1785.22,2227.46 r180 bottom
C10 "GCM21BR71A106KE22L" 0805_HV 1931.22,2227.46 r0 bottom
C11 "GCM21BR71A106KE22L" 0805_HV 1785.22,1831.32 r180 bottom
C12 "GCM21BR71A106KE22L" 0805_HV 1933.22,1831.46 r0 bottom
C13 "GCM31CR71A226KE02" 1206_180 1815.88,2387.1 r90 bottom
C14 "GCM31CR71A226KE02" 1206_180 1904.88,2386.1 r90 bottom locked
C15 "GCM31CR71A226KE02" 1206_180 1812.7,1672.1 r270 bottom
C16 "GCM31CR71A226KE02" 1206_180 1904.7,1674.1 r270 bottom
C17 "GCM155R71C224KE02D" 0402L 2022.22,2038.46 r180 bottom
C18 "CGA2B2NP01H391J050BA" 0402L 1658.54,2210.38 r270 bottom
C19 "CGA2B2NP01H391J050BA" 0402L 2066.22,2229.46 r270 bottom
C20 "CGA2B2NP01H391J050BA" 0402L 1654.22,1837.15 r90 bottom
C21 "CGA2B2NP01H391J050BA" 0402L 2068.22,1839.46 r90 bottom
C22 "597D476X9050Z2T" 597D_Z 2279.37,259.06 r270 top
C23 "597D476X9050Z2T" 597D_Z 2004.37,259.06 r270 top
C24 "GCM155R71C104KA55D" 0402L 2595.37,2038.06 r90 bottom
C25 "CGA2B3X7R1H104K050BB" 0402L 1904.09,2646.69 r90 bottom
C26 "CGA2B3X7R1H104K050BB" 0402L 1689.22,1497.52 r90 top
C27 "C0402C104K8RACTU" 0402 790,2330 r0 top
C28 "CL10B105KQ8NNNC" 0603 900.37,2666.8 r270 bottom
C29 "GRM188R70J104KA01D" 0603 912.37,2965 r90 bottom
C30 "CGA2B3X7S2A102K050BB" 0402 807.1,2956.6 r90 bottom
C31 "GCM188R71C105KA64D" 0603 569,1069 r270 bottom
C32 "C0402C104K8RACTU" 0402L 1615.49,2888.76 r90 bottom
C33 "C0402C104K8RACTU" 0402L 1306.37,2879.06 r90 bottom
C34 "C0402C104K8RACTU" 0402L 1277.37,3692.06 r180 bottom
C35 "C1005X7S0J105M050BC" 0402L 1435.49,3674.16 r270 bottom
C36 "C0402C104K8RACTU" 0402L 966.8,3243.99 r0 top
C37 "C1005X7S0J105M050BC" 0402L 1031.37,3111.06 r90 bottom
C38 "C1005X7R1E103K050BB" 0402L 1210.37,2890.06 r0 bottom
C39 "C1005X7S1A225K050BC" 0402_065L 1820.49,3303.76 r270 bottom
C40 "C0402C104K8RACTU" 0402L 1775.49,3303.76 r270 bottom
C41 "C1005X7S0J105M050BC" 0402L 1345.37,2879.06 r90 bottom
C42 "C0402C103K4RACTU" 0402L 2505.22,3432.34 r180 top
C43 "C0402C104K8RACTU" 0402L 1715.49,2923.76 r90 bottom
C44 "C0402C104K8RACTU" 0402L 1770.49,3478.76 r270 bottom
C45 "C0402C104K8RACTU" 0402L 960,3115 r0 bottom
C46 "C0402C103K4RACTU" 0402L 953.17,3169.06 r0 bottom
C47 "GRM1555C1H8R0DA01D" 0402L 1895,3065 r90 bottom
C48 "GRM1555C1H8R0DA01D" 0402L 1838,3246 r180 bottom
C49 "C0402C104K8RACTU" 0402L 1640.09,2002.2 r90 top
C50 "C0402C104K8RACTU" 0402L 334.43,2227.8 r90 top
C51 "C1608X7S1A475K080AC" 0603 1675,3105 r0 top
C52 "C0402C104K8RACTU" 0402 1665,3160 r180 top
C53 "C1608X7S1A475K080AC" 0603 1719.85,3339.59 r90 top
C54 "C0402C104K8RACTU" 0402 1659.85,3329.59 r270 top
C55 "C0402C104K8RACTU" 0402 1835,2790 r180 top
C56 "C0402C104K8RACTU" 0402 1607.78,3329.18 r270 top
C57 "C0402C104K8RACTU" 0402 1496.69,2971.95 r0 top
C58 "C1608X7S1A475K080AC" 0603 971.5,2985 r180 top
C59 "C0402C104K8RACTU" 0402 975,3040 r180 top
C60 "GRM1555C1H8R0DA01D" 0402 1800,2978 r0 top
C61 "GRM1555C1H8R0DA01D" 0402 1805,2924 r0 top
C62 "C1005X7S1A225K050BC" 0402_065 1184.37,2720.06 r180 top
C63 "C0402C104K8RACTU" 0402 2431.37,4033.95 r180 bottom
C64 "04025A150FAT2A" 0402 1275.51,2651.19 r270 bottom
C65 "C1005X7S1A225K050BC" 0402_065 1230,2621.38 r270 top
C66 "GCM188R71C105KA64D" 0603 1422.78,3614.18 r90 top
C67 "C0402C104K8RACTU" 0402 1162.78,3604.18 r90 top
C68 "C0402C104K8RACTU" 0402 1334.37,2966.18 r0 top
C69 "GCM188R71C105KA64D" 0603 1100,2910 r270 top
C70 "C0402C104K8RACTU" 0402 1189.16,2969.18 r0 top
C71 "CGA2B3X7R1H104K050BB" 0402 1457.26,1501.13 r180 bottom
C72 "C0402C104K8RACTU" 0402 474.37,2154.68 r90 top
C73 "C0402C104K8RACTU" 0402 785.63,2482 r0 top
C74 "CGA2B3X7R1H104K050BB" 0402 1246.81,1623.78 r90 bottom
C75 "C0603C225K8PACTU" 0603 992.37,1700.06 r270 bottom
C76 "C0603C225K8PACTU" 0603 1107.13,1765.91 r180 bottom
C77 "CGA2B3X7R1H104K050BB" 0402 1114.62,1756.53 r180 top
C78 "JMK105B7474KVHF" 0402 2154.37,1089.06 r90 top
C79 "EEE-FK1H100UR" SM_RADIAL_C 2204.37,571.14 r0 top
C80 "GRM32ER71H106MA12" 1210_270 2079.37,744.06 r0 top
C81 "C1210C104K5RACTU" 1210 2079.37,879.06 r0 top
C82 "C0805C103K5RACTU" 0805_HV 2069.37,989.06 r0 top
C83 "GRM32ER71H106MA12" 1210_270 2151.37,1560.06 r0 top
C84 "C1210C104K5RACTU" 1210 2150.37,1435.06 r0 top
C85 "C0805C103K5RACTU" 0805_HV 2090.37,1318.06 r0 top
C86 "0402YC104KAT2A" 0402 1859.37,1154.06 r90 top
C87 "C2012X7R1E475K125AB" 0805_HV 1879.37,1024.06 r180 top
C88 "C1005X7S1A225K050BC" 0402_065L 732.41,1215 r0 top
C89 "CL32B226KOJNFNE" 1210_270 2244.37,979.06 r270 top
C90 "CL32B226KOJNFNE" 1210_270 2379.37,979.06 r270 top
C91 "CL32B226KOJNFNE" 1210_270 2364.37,1419.06 r90 top
C92 "C0402C104K8RACTU" 0402 1520.04,2533.13 r0 bottom
C93 "C0402C104K8RACTU" 0402 1310.37,2418.06 r180 bottom
C94 "C0402C104K8RACTU" 0402 728.37,2141.06 r180 top
C95 "C0402C104K8RACTU" 0402 1360,2220 r0 bottom
C96 "JMK105B7474KVHF" 0402 1479.37,1134.06 r90 top
C97 "EEE-FK1H100UR" SM_RADIAL_C 1679.37,854.06 r270 top
C98 "GRM32ER71H106MA12" 1210_270 1082,1020.03 r90 top
C99 "C1210C104K5RACTU" 1210 944.37,1019.06 r90 top
C100 "C0805C103K5RACTU" 0805_HV 1194.37,1004.06 r90 top
C101 "GRM32ER71H106MA12" 1210_270 1599.37,1119.06 r90 top
C102 "C1210C104K5RACTU" 1210 1724.37,1119.06 r90 top
C103 "C0805C103K5RACTU" 0805_HV 1484.37,999.06 r90 top
C104 "0402YC104KAT2A" 0402 1349.37,819.06 r180 top
C105 "CL32B226KOJNFNE" 1210_270 1237.53,1419.87 r90 top
C106 "CL32B226KOJNFNE" 1210_270 1549.37,1314.06 r0 top
C107 "CL32B226KOJNFNE" 1210_270 1372.99,1420.82 r90 top
C108 "C2012X7R1E475K125AB" 0805_HV 1469.37,839.06 r270 top
C109 "C0603C104J3RACTU" 0603 532.7,904.23 r180 top
C110 "CGA2B3X7S2A102K050BB" 0402 564.7,980.09 r0 bottom
C111 "GCM188R71C105KA64D" 0603 643.37,1678.06 r270 top
C112 "C0603C104J3RACTU" 0603 550.37,1990.55 r90 top
C113 "CGA2B3X7S2A102K050BB" 0402 737.99,1815.06 r180 bottom
C114 "C0402C104K8RACTU" 0402 1450,2057 r0 bottom
C115 "C0402C104K8RACTU" 0402 1281.37,2054.06 r180 bottom
C116 "C0402C104K8RACTU" 0402 849.75,1890.06 r180 bottom
C117 "C0402C104K8RACTU" 0402 765.61,2001.06 r90 top
C119 "C0402C330J5GAC" 0402L 746.63,1428 r180 bottom
C120 "C1005X7S0J105M050BC" 0402L 742.53,1392.79 r0 top
"CAUTION HOT SURFACE1" "CAUTION HOT SURFACE" IEC_HotSurface_Small 2183,2649.66 r0 top
D1 "SMBJ30A-13-F" SMB 2166,109 r180 bottom
D4 "TLMY1000-GS08" TLMx1000_Yellow 2596.57,4265.06 r0 top
D5 "TLMY1000-GS08" TLMx1000_Yellow 761,118.11 r270 top
D6 "TLMY1000-GS08" TLMx1000_Yellow 829.95,118.11 r270 top
D7 "TLMY1000-GS08" TLMx1000_Yellow 898.94,118.11 r270 top
D8 "TLMS1000-GS08" TLMx1000_Red 970,118.11 r270 top
D9 "TLMS1000-GS08" TLMx1000_Red 2619.86,4338.43 r180 top
D10 "TLMS1000-GS08" TLMx1000_Red 693,118.11 r270 top
D11 "SML-P12PTT86" SML-P1_GREEN 2572.7,744.06 r270 top
D14 "SML-P12PTT86" SML-P1_GREEN 2644.37,744.06 r270 top
Designator1 "Comment" STANDOFF_FAB_0022 1476.38,250 r180 bottom locked
DS1 "TLMY1000-GS08" TLMx1000_Yellow 2655,1795 r180 top
DS2 "TLMY1000-GS08" TLMx1000_Yellow 2685,4445 r90 top
DS3 "TLMS1000-GS08" TLMx1000_Red 624,118.11 r270 top
DS4 "TLMS1000-GS08" TLMx1000_Red 554,118.11 r270 top
F1 "0440005.WR" 1206 2474.37,174.06 r90 top
FB1 "BLM21PG300SH1D" 0805_HV 2269.37,329.06 r90 bottom
FB2 "BLM21PG300SH1D" 0805_HV 2359.37,329.06 r90 bottom
FID1 "Fiducial" Fiducial10-20 2572,4917 r0 top
FID2 "Fiducial" Fiducial10-20 137,4846 r180 bottom
FID3 "Fiducial" Fiducial10-20 2572,4917 r90 bottom
FID4 "Fiducial" Fiducial10-20 137,4846 r90 top
FID5 "Fiducial" Fiducial10-20 96,112 r90 top
FID6 "Fiducial" Fiducial10-20 96,112 r90 bottom
J1 "OSTTE030161" On-Shore_OSTTE030161 2595,1490 r90 top
J2 "OSTTE030161" On-Shore_OSTTE030161 2595,1045 r90 top
J3 "128-0711-201" Johnson_128-0711-201 2570,4645 r90 top
J4 "QTH-030-01-L-D-A" Samtec_QTH-030-01-x-D-A 1960,4340.95 r90 top locked
J5 "SSM-110-S-DV" Samtec_SSM-110-x-DV 418.85,3193 r270 bottom locked
J6 "SSM-110-S-DV" Samtec_SSM-110-x-DV 2118.85,3193 r270 bottom locked
J7 "SSM-103-S-SV" Samtec_SSM-103-x-SV 377.61,2443 r270 bottom
J8 "SSM-103-S-SV" Samtec_SSM-103-x-SV 2160.09,2443 r270 bottom
J9 "QSH-030-01-L-D-A" Samtec_QSH-030-01-X-D-A 256.37,1582.06 r180 top
J10 "QSH-030-01-L-D-A" Samtec_QSH-030-01-X-D-A 516.3,2960.59 r0 top
J11 "105017-0001" CONN_105017-0001 2645.84,3279.39 r270 bottom
J12 "105017-0001" CONN_105017-0001 2645.84,3954.39 r270 bottom
J13 "22284033" Molex_0022284033 990,2720 r90 top
J14 "22284033" Molex_0022284033 2382.37,2974.06 r270 bottom
J15 "22284033" Molex_0022284033 1869.37,3589.06 r90 bottom
J16 "TSW-105-07-G-D" TSW-105-07-G-D 705,385 r0 top
J17 "QTH-030-01-L-D-A" Samtec_QTH-030-01-x-D-A 668.5,4340.95 r270 top
J18 "TSW-108-07-G-D" TSW-108-07-G-D 705,607 r0 top
J19 "TSW-107-07-L-D-006" Samtec_TSW-107-07-L-D-006 2607,2641 r180 top
J20 "TSW-108-07-G-D" TSW-108-07-G-D 1515,602 r0 top
J27 "22284033" Molex_0022284033 813,1011 r270 top
J28 "22284033" Molex_0022284033 879.37,1604.06 r270 top
L1 "DFE252012P-R47M=P2" DFE252012P 1720.88,2333.46 r90 bottom
L2 "DFE252012P-R47M=P2" DFE252012P 2003.22,2333.46 r90 bottom
L3 "DFE252012P-R47M=P2" DFE252012P 1714.65,1725.46 r270 bottom
L4 "DFE252012P-R47M=P2" DFE252012P 2004.22,1725.46 r270 bottom
L5 "BLM15HG601SN1D" 0402 1680,3050 r180 top
L6 "BLM15HG601SN1D" 0402 1779.85,3334.59 r270 top
L7 "LQM21PN1R0MC0D" 0805_HV 993.37,1706.06 r90 top
L8 "XAL5030-222MEB" XAL5030 2304.37,1199.06 r0 top
L9 "XAL5030-222MEB" XAL5030 1334.37,1199.06 r90 top
LBL1 "THT-14-423-10" Label_650x200 1609,4377 r90 top
Logo1 "Texas Instruments" TI_Stacked_Overlay_Small 463,3648 r0 top
Logo2 "CE Mark" CE_Mark_5mm 214,2446 r0 top
Logo3 "FCC disclaimer" FCC_disclaimer 2708,2999 r90 top
Logo4 "WEEE logo" WEEE_Minimum 2400,3675 r0 top
MH1 "Comment" MTGNP431H431 136,5170 r0 top locked
MH2 "Comment" MTGNP431H431 2365,5190 r0 top locked
MH3 "Comment" MTGNP431H431 132.9,2146.53 r0 top locked
MH4 "Comment" MTGNP431H431 2372.9,2146.53 r0 top locked
P1 "TSW-102-07-G-S" TSW-102-07-X-S 895.63,1336 r90 top
P2 "PJ-002AH" CUI_PJ-002AH 2576.85,459.02 r0 top
P3 "TSW-102-07-G-S" TSW-102-07-X-S 1994.37,574.06 r270 top
P4 "TSW-102-07-G-S" TSW-102-07-X-S 148.37,676.66 r180 top
P5 "TSW-102-07-G-S" TSW-102-07-X-S 148.37,476.8 r180 top locked
P6 "TSW-102-07-G-S" TSW-102-07-X-S 148.37,279.06 r180 top
P7 "TSW-102-07-G-S" TSW-102-07-X-S 1889.37,819.06 r270 top
Q1 "BSS123" SOT-23 2505.37,1786.06 r0 top locked
Q2 "BSS123" SOT-23 2565,4475 r0 top
R1 "ERJ-2GE0R00X" 0402 1624,1836.85 r270 top
R2 "CRCW040261R9FKED" 0402L 2408,1485 r0 bottom
R3 "ERJ-2GE0R00X" 0402L 1575,1835.85 r270 top
R4 "CRCW040210K0FKED" 0402L 1520,1825 r0 bottom
R5 "CRCW040210K0FKED" 0402L 1530,1880 r270 bottom
R6 "ERJ-2GE0R00X" 0402 1603,1753.85 r180 top
R7 "CRCW040261R9FKED" 0402L 2408,1525 r180 bottom
R8 "ERJ-2GE0R00X" 0402 1596,1931.85 r180 top
R9 "CRCW040210K0FKED" 0402 1923.63,4642 r90 bottom
R10 "ERJ-2GEJ511X" 0402 761.6,217.3 r270 top
R11 "CRCW040261R9FKED" 0402 1458.17,1649.28 r180 bottom
R12 "ERJ-2GE0R00X" 0402 1458.17,1699.28 r0 bottom
R13 "CRCW040210K0FKED" 0402 1949.63,4538.38 r270 bottom
R14 "CRCW02010000Z0ED" 0201_Silk 2460,4632.01 r90 top
R15 "ERJ-2GE0R00X" 0402 1458.17,1549.28 r0 bottom
R16 "CRCW04024K70JNED" 0402 543.87,2155.06 r270 top
R17 "CRCW04024K70JNED" 0402 783.63,2524 r180 bottom locked
R18 "CRCW040210K0FKED" 0402L 1305,2141.06 r0 top
R19 "CRCW040210K0FKED" 0402L 1298.73,2055 r0 top
R20 "ERJ-2GE0R00X" 0402 528.26,1343.95 r180 top
R21 "ERJ-2GE0R00X" 0402 528.26,1393.95 r180 top
R22 "CRCW040210K0FKED" 0402 2069.01,4516.99 r180 bottom
R23 "CRCW040210K0FKED" 0402L 873.1,1945 r180 bottom
R24 "CRCW040210K0FKED" 0402L 1267,2240 r90 top
R25 "CRCW040210K0FKED" 0402L 837.37,2164.37 r90 top
R26 "CRCW040210K0FKED" 0402L 784.63,2482 r180 bottom
R27 "ERJ-2GE0R00X" 0402 528.26,1443.95 r180 top
R28 "ERJ-2GE0R00X" 0402 528.26,1493.95 r180 top
R29 "ERJ-2GE0R00X" 0402 528.26,1548.95 r180 top
R30 "ERJ-2GE0R00X" 0402 528.26,1598.95 r180 top
R31 "CRCW040261R9FKED" 0402 1458.17,1599.28 r0 bottom
R32 "ERJ-2GE0R00X" 0402 1266.81,1543.78 r180 bottom
R33 "ERJ-2GE0R00X" 0402 1301.81,1623.78 r270 bottom
R34 "ERJ-2GEJ101X" 0402 2476.37,2487.43 r270 bottom
R35 "ERJ-2GE0R00X" 0402 617,773 r270 bottom
R36 "ERJ-2GE0R00X" 0402 567,773 r90 bottom
R37 "CRCW040210K0FKED" 0402L 832.96,2043.11 r90 bottom
R38 "ERJ-2GE0R00X" 0402 723.19,771.65 r270 bottom
R39 "ERJ-2GE0R00X" 0402 668.19,771.65 r90 bottom
R40 "ERJ-2GE0R00X" 0402 789.37,769.06 r270 bottom
R41 "CRCW04024K70JNED" 0402 834.37,2041.06 r90 top
R42 "ERJ-2GE0R00X" 0402 849.37,769.06 r90 bottom
R43 "ERJ-2GE0R00X" 0402 977.37,3349.06 r180 bottom
R44 "ERJ-2GE0R00X" 0402 2467.37,2755.06 r270 bottom
R45 "ERJ-2GE0R00X" 0402 949.37,772.68 r270 bottom
R46 "ERJ-2GE0R00X" 0402 1004.37,772.68 r90 bottom
R47 "ERJ-2GE0R00X" 0402 1499.37,2875.06 r180 bottom
R48 "ERJ-2GE0R00X" 0402 1421.37,2860.06 r90 bottom
R49 "PMR18EZPFV2L00" 1206 611.37,1189.06 r180 bottom
R50 "PMR18EZPFV2L00" 1206 519.37,1748.06 r90 bottom
R51 "CRCW040210K0FKED" 0402L 2665,2235 r180 bottom
R52 "ERJ-2GE0R00X" 0402 1166.37,736.85 r0 bottom
R53 "ERJ-2GE0R00X" 0402 1057.15,771.65 r90 bottom
R54 "ERJ-2GE0R00X" 0402 528.26,1803.95 r180 top
R55 "CRCW0402100KFKED" 0402L 187,3443 r180 bottom
R56 "CRCW0402100KFKED" 0402L 186.32,3342 r180 bottom
R57 "CRCW040210K0FKED" 0402L 202.06,2808.06 r0 bottom
R58 "CRCW040210K0FKED" 0402L 200.37,2702.06 r0 bottom
R59 "CRCW20100000Z0EF" 2010 756.37,3616.06 r0 bottom
R60 "CRCW040210K0FKED" 0402L 2010,3500 r0 top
